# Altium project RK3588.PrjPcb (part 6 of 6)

## Sheet VSC_DP.SchDoc
size D; SheetNumber: 21; SheetTotal: 22
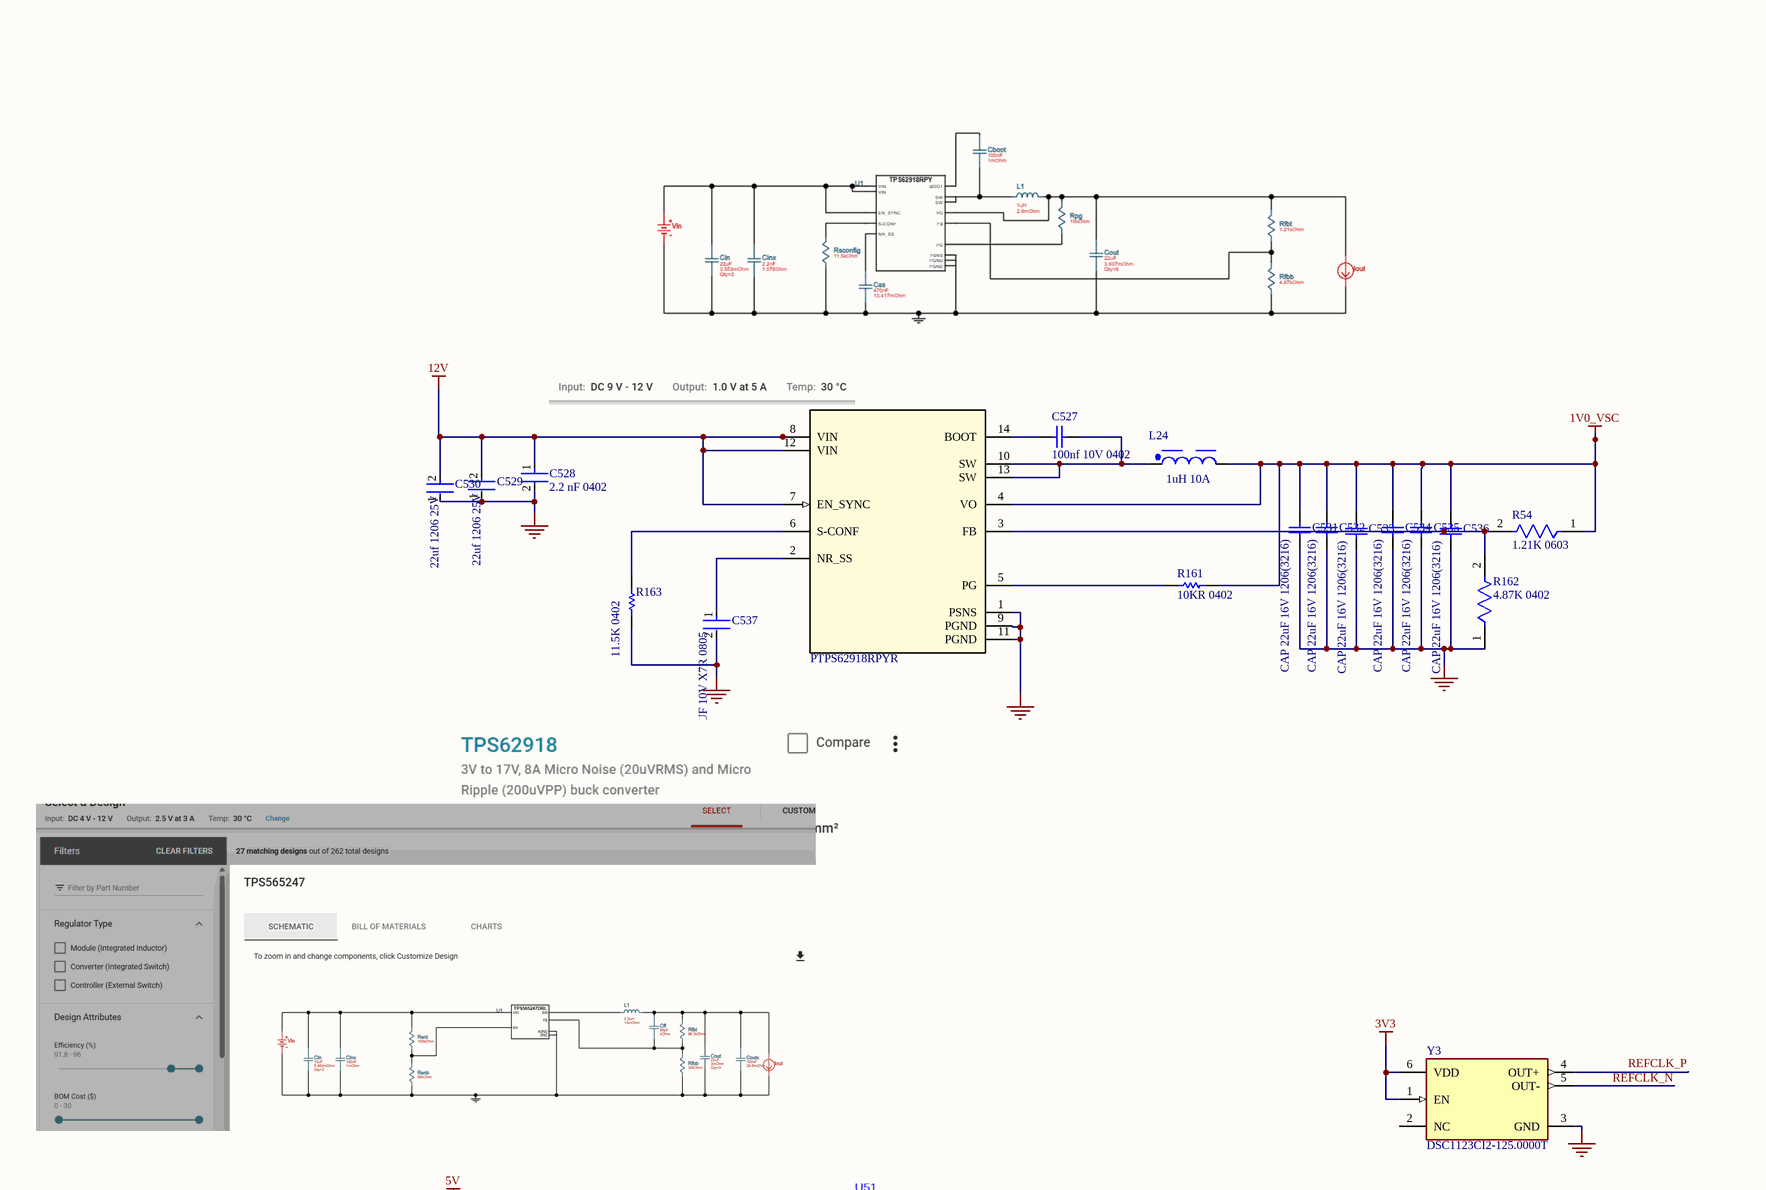
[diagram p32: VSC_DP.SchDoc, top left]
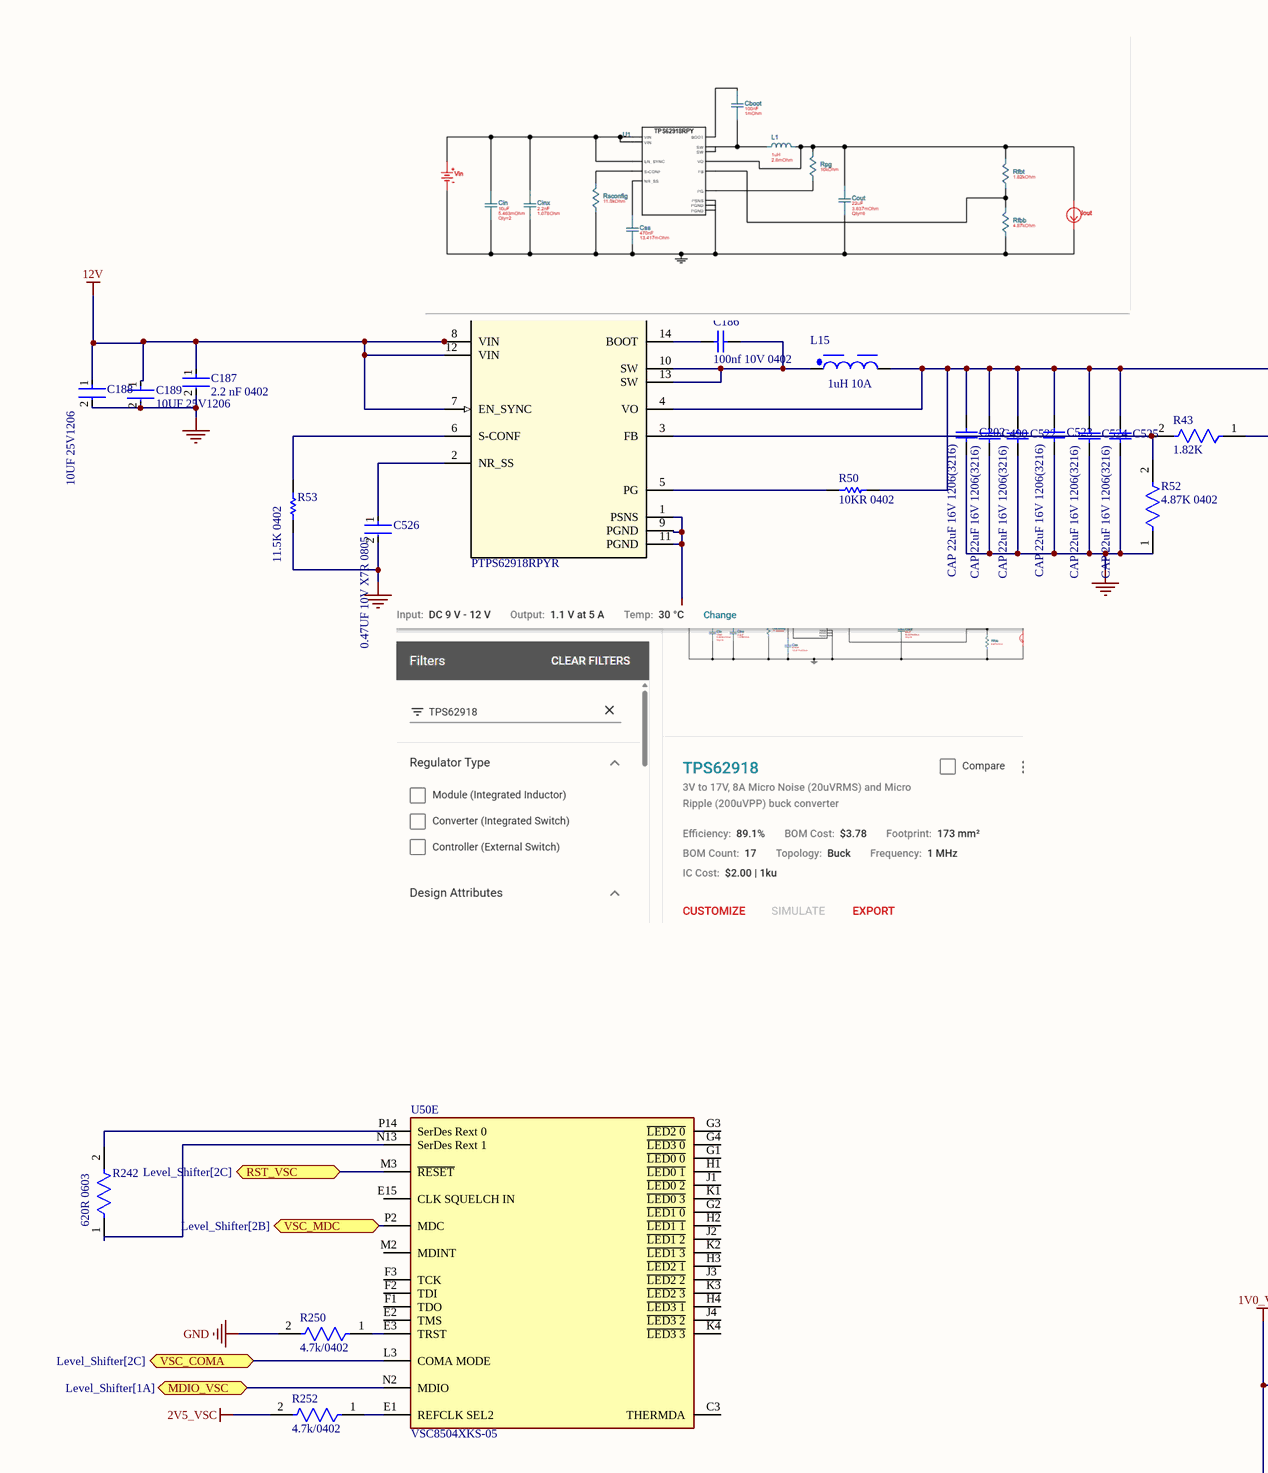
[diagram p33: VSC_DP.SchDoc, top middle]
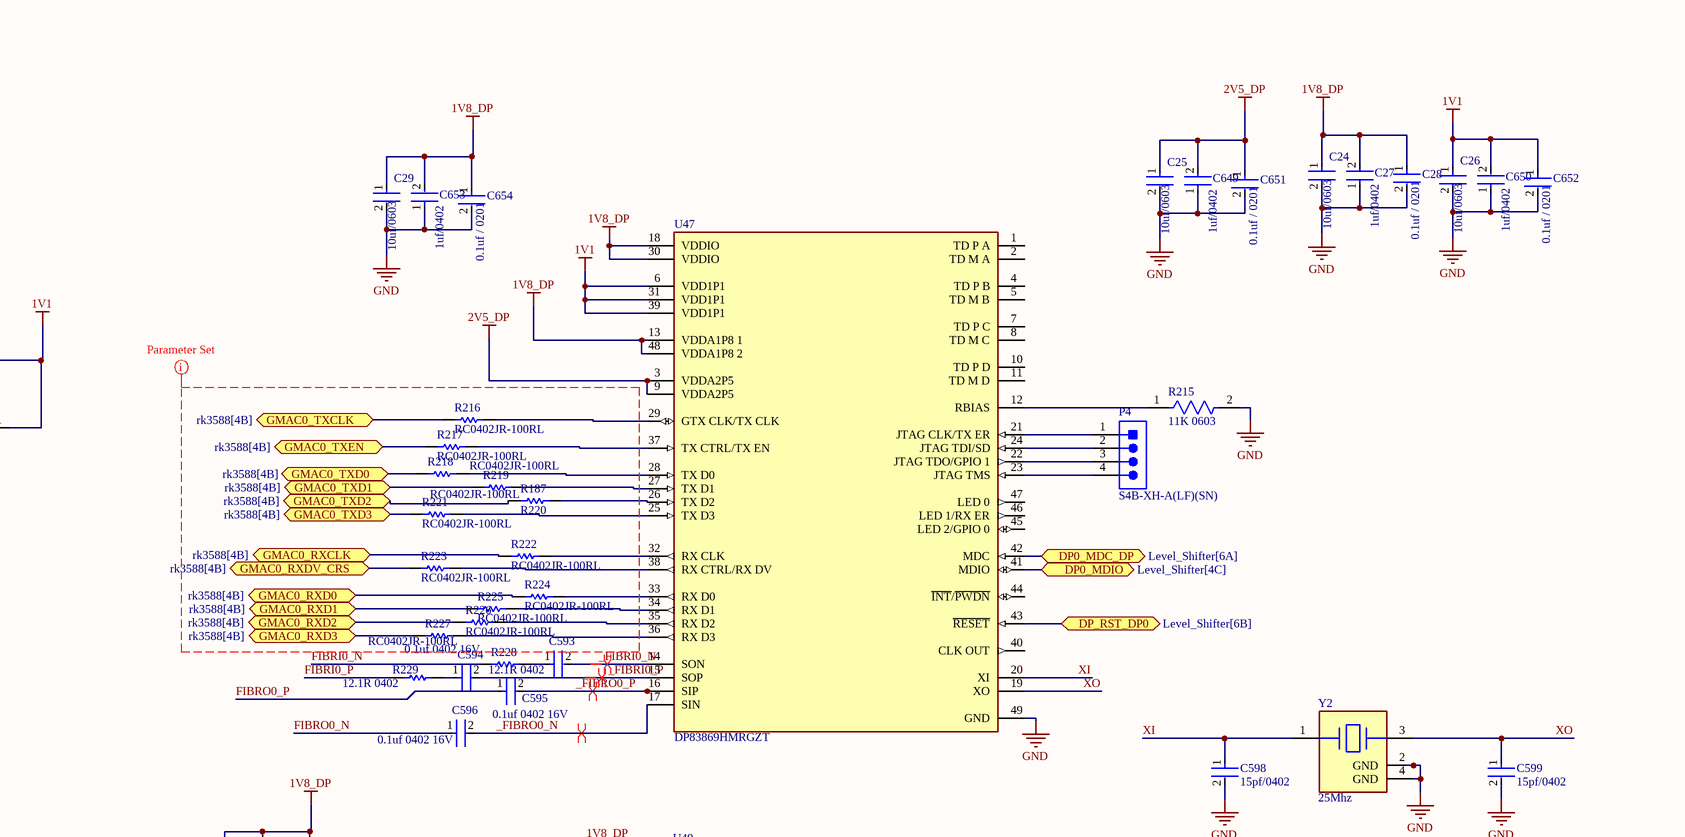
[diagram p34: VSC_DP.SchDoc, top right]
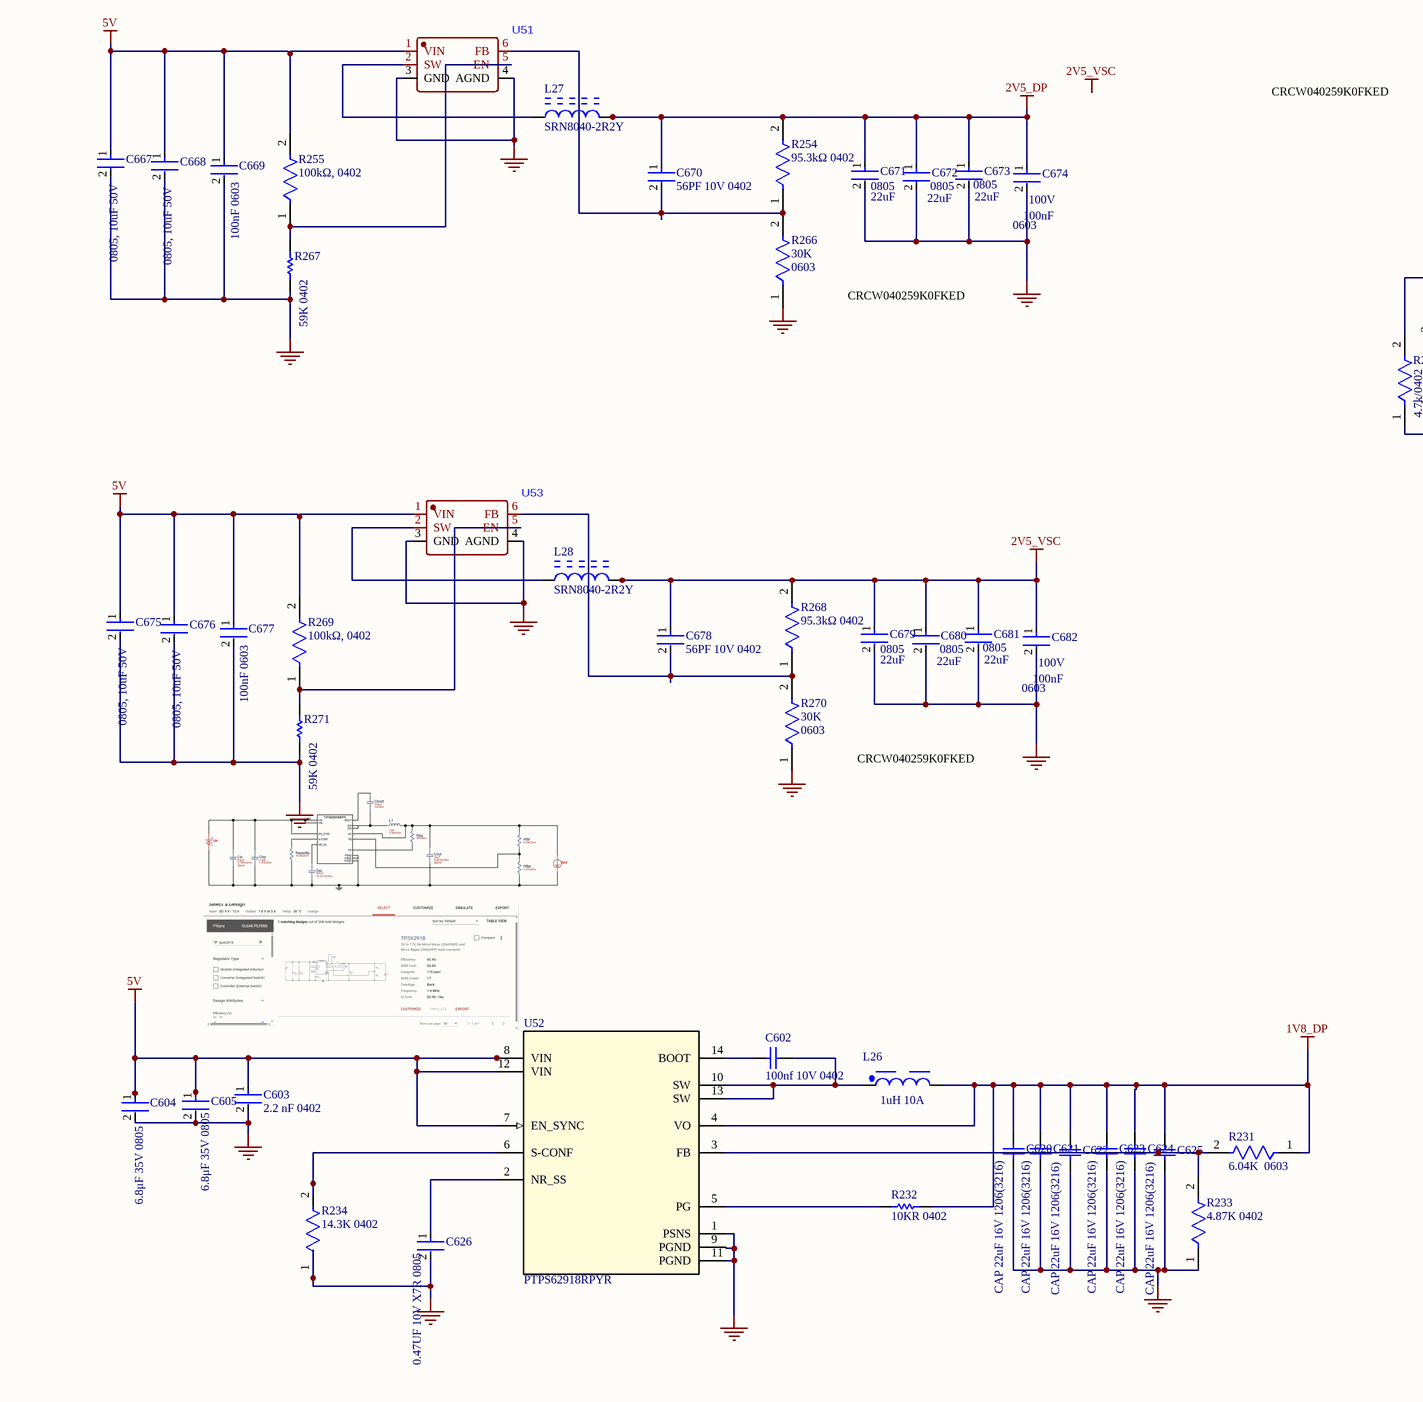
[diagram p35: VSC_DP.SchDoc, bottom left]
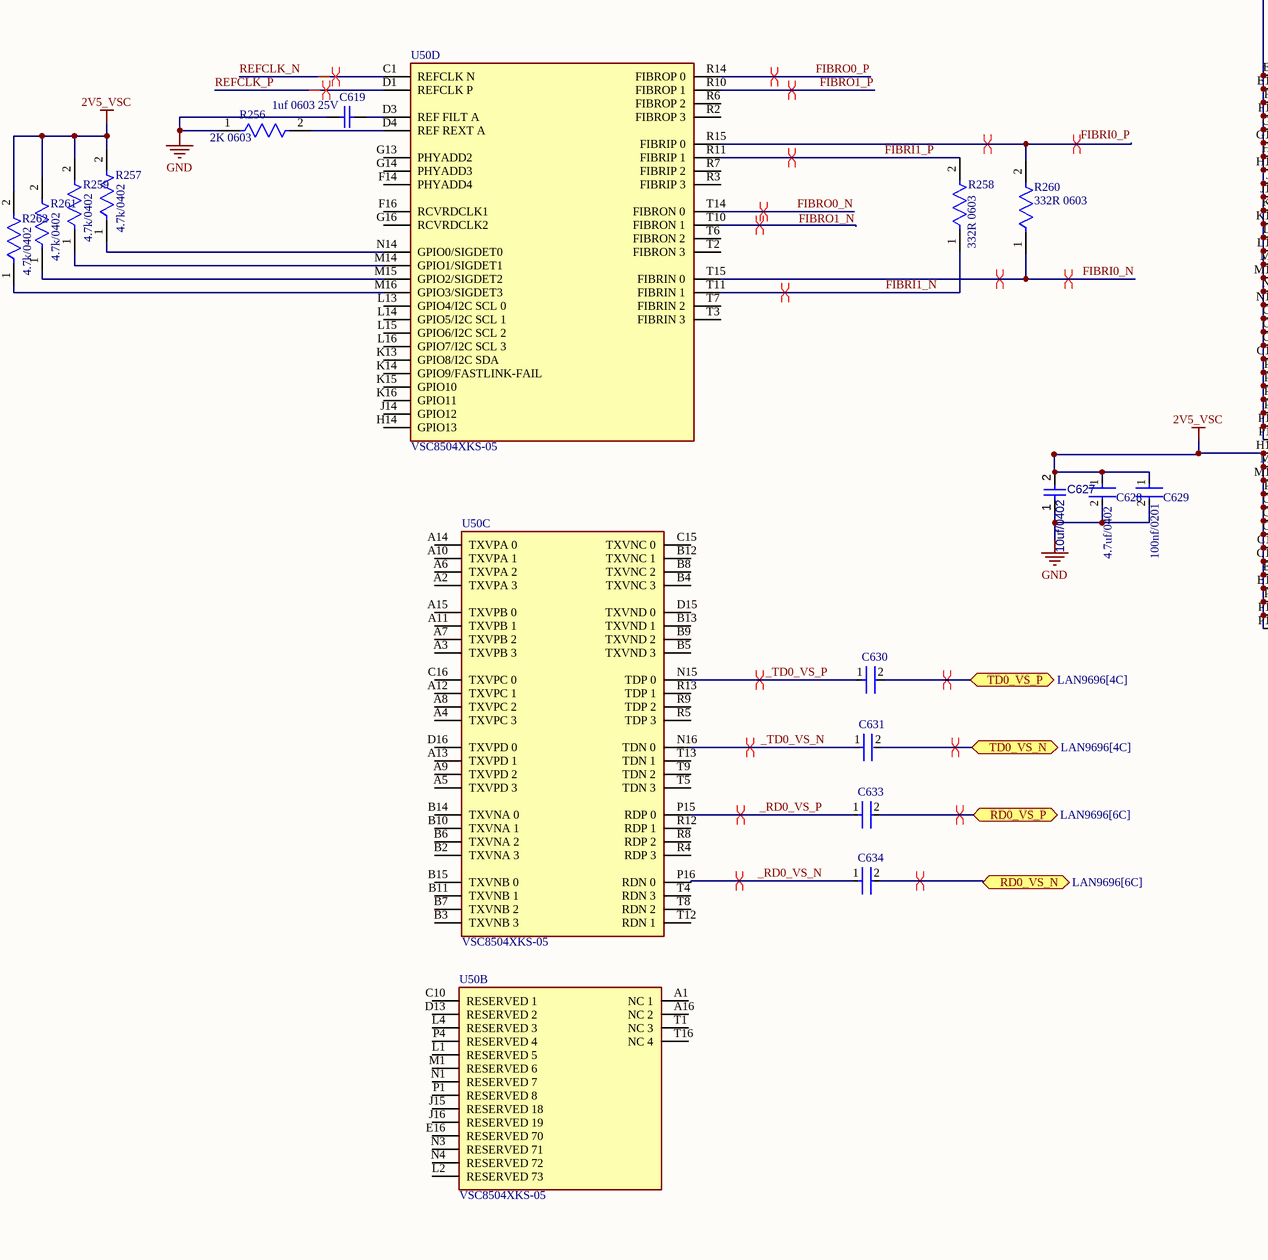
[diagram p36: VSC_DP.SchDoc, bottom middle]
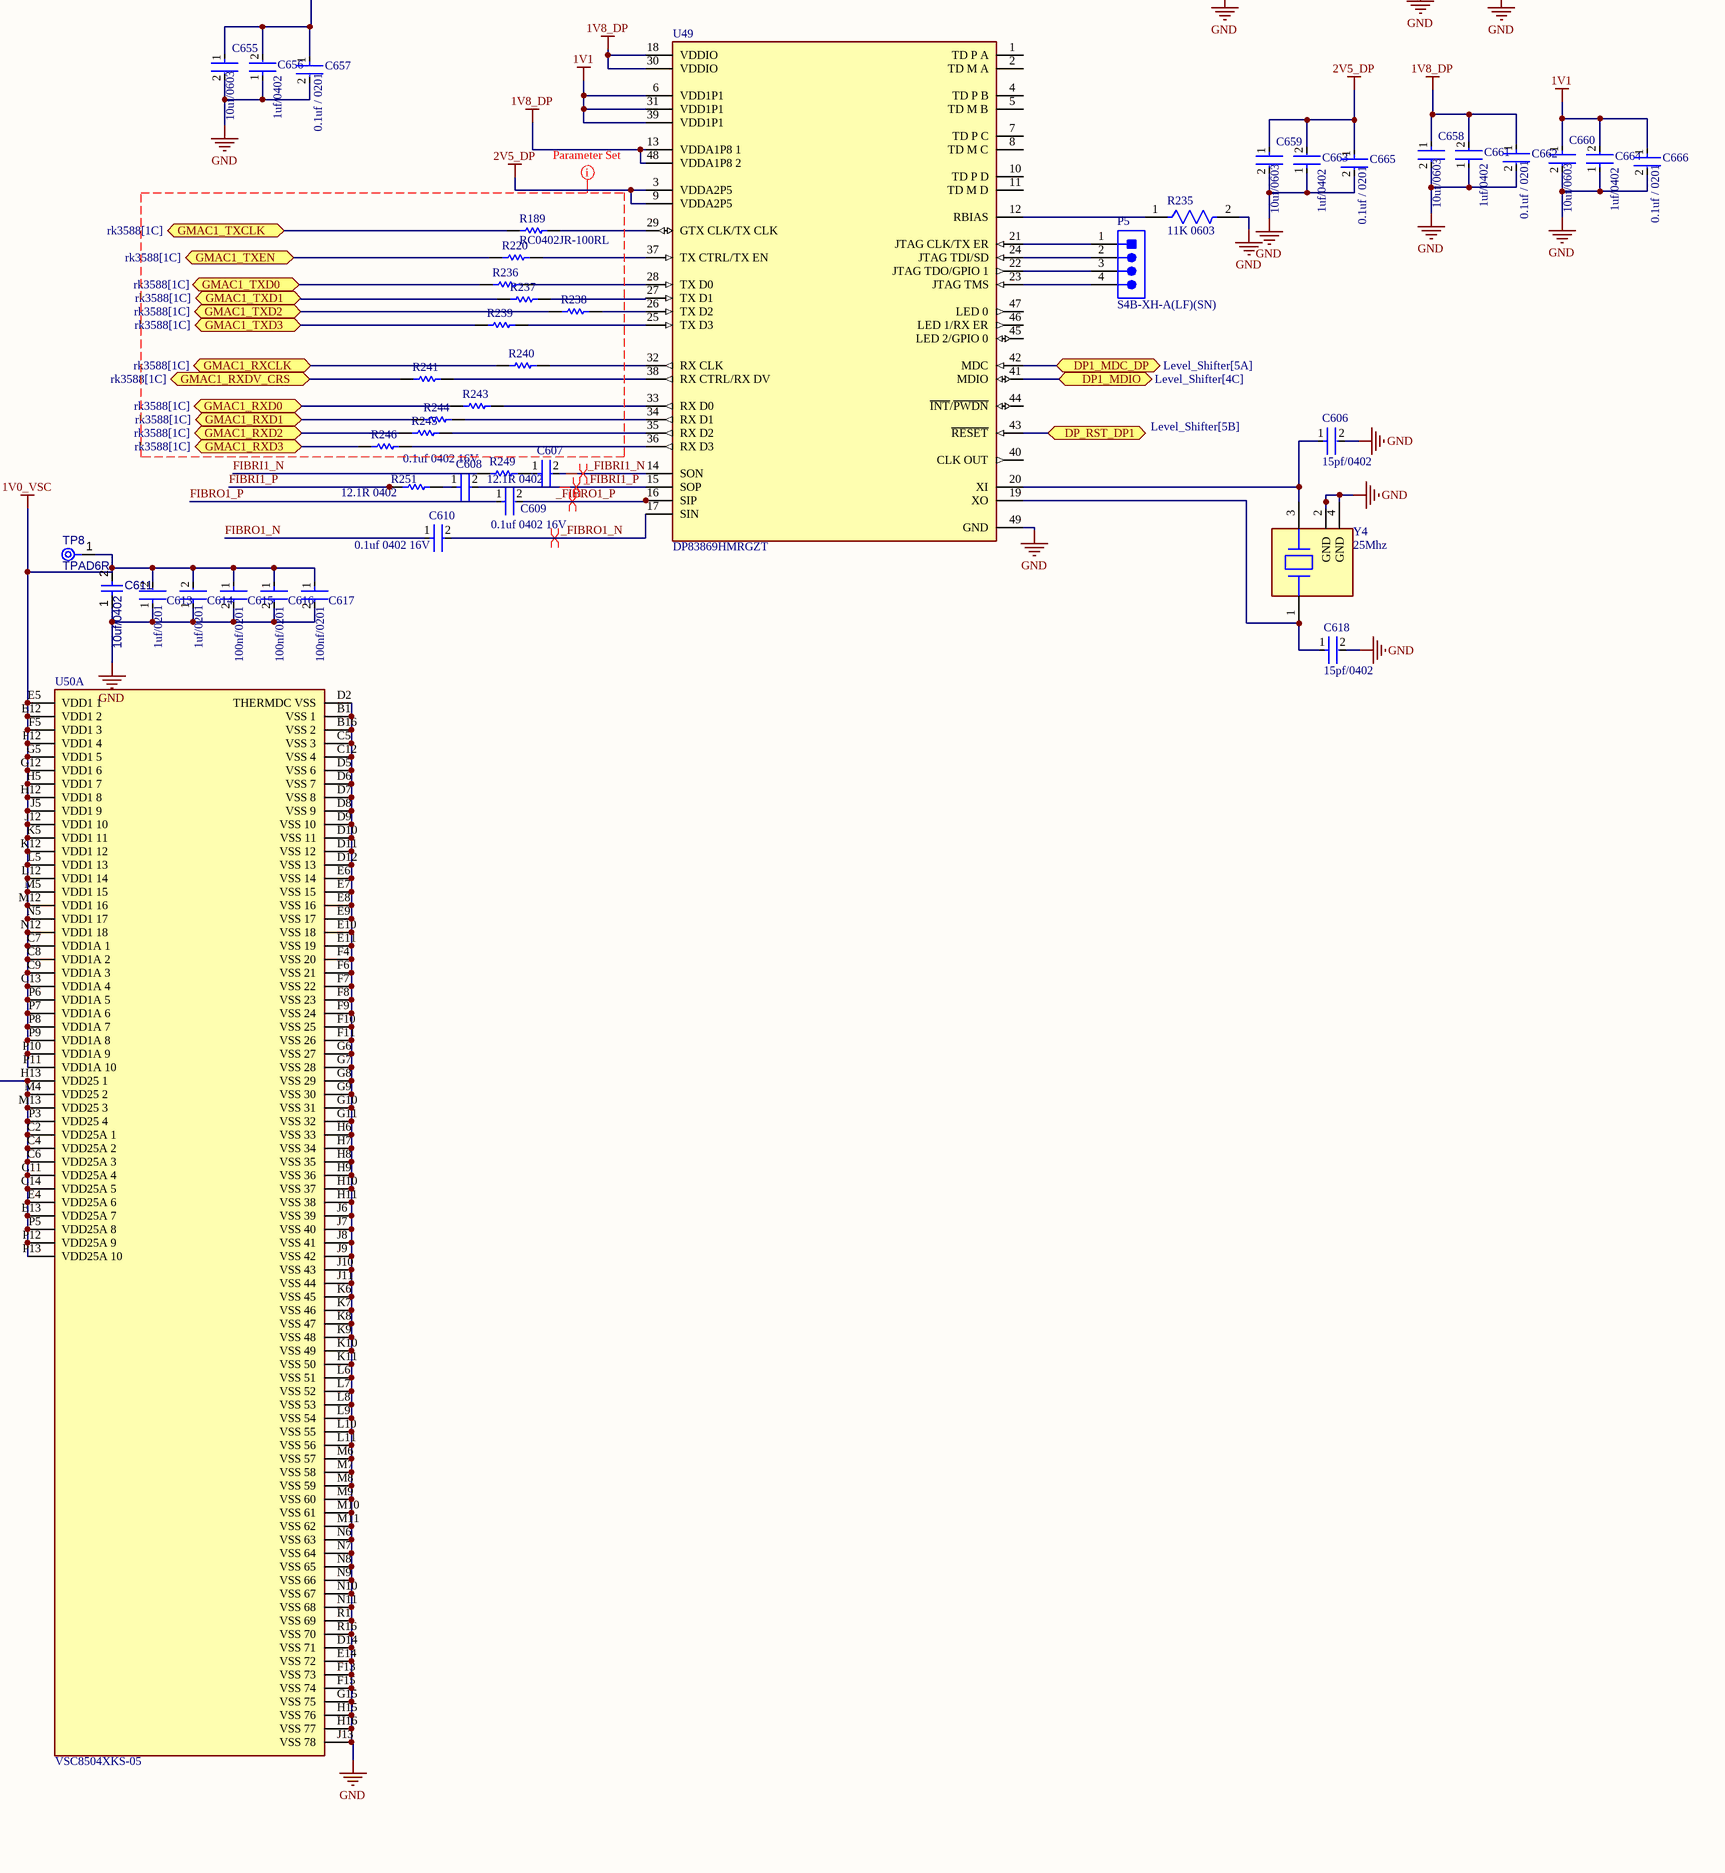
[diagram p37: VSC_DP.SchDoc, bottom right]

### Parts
C24  10uf/0603  [FP-CC0603-DC-MFG]
C25  10uf/0603  [FP-CC0603-DC-MFG]
C26  10uf/0603  [FP-CC0603-DC-MFG]
C27  1uf/0402  [FP-C0402C-BB-IPC_B]
C28  0.1uf / 0201  [FP-CC0201-BB-MFG]
C29  10uf/0603  [FP-CC0603-DC-MFG]
C186  100nf 10V 0402  [CAPC1005X55X25LL05T10]
C187  2.2 nF 0402  [FP-CGA2B-IPC_B]
C188  10UF 25V1206  [FP-C1206C-EH-MFG]
C189  10UF 25V1206  [FP-C1206C-EH-MFG]
C202  CAP 22uF 16V 1206(3216)  [CAPC1206(3216)190_L]
C490  CAP 22uF 16V 1206(3216)  [CAPC1206(3216)190_L]
C522  CAP 22uF 16V 1206(3216)  [CAPC1206(3216)190_L]
C523  CAP 22uF 16V 1206(3216)  [CAPC1206(3216)190_L]
C524  CAP 22uF 16V 1206(3216)  [CAPC1206(3216)190_L]
C525  CAP 22uF 16V 1206(3216)  [CAPC1206(3216)190_L]
C526  0.47UF 10V X7R 0805  [FP-C0805C-DN-MFG]
C527  100nf 10V 0402  [CAPC1005X55X25LL05T10]
C528  2.2 nF 0402  [FP-CGA2B-IPC_B]
C529  22uf 1206 25V  [FP-GRM31C-0_3-e0_3_0_8-IPC_A]
C530  22uf 1206 25V  [FP-GRM31C-0_3-e0_3_0_8-IPC_A]
C531  CAP 22uF 16V 1206(3216)  [CAPC1206(3216)190_L]
C532  CAP 22uF 16V 1206(3216)  [CAPC1206(3216)190_L]
C533  CAP 22uF 16V 1206(3216)  [CAPC1206(3216)190_L]
C534  CAP 22uF 16V 1206(3216)  [CAPC1206(3216)190_L]
C535  CAP 22uF 16V 1206(3216)  [CAPC1206(3216)190_L]
C536  CAP 22uF 16V 1206(3216)  [CAPC1206(3216)190_L]
C537  0.47UF 10V X7R 0805  [FP-C0805C-DN-MFG]
C593  0.1uf 0402 16V  [FP-C0402-BB-MFG]  (value not drawn)
C594  0.1uf 0402 16V  [FP-C0402-BB-MFG]
C595  0.1uf 0402 16V  [FP-C0402-BB-MFG]
C596  0.1uf 0402 16V  [FP-C0402-BB-MFG]
C598  15pf/0402  [FP-C0402-BB-MFG]
C599  15pf/0402  [FP-C0402-BB-MFG]
C602  100nf 10V 0402  [CAPC1005X55X25LL05T10]
C603  2.2 nF 0402  [FP-CGA2B-IPC_B]
C604  6.8μF 35V 0805  [FP-C2012-125-0_2-IPC_B]
C605  6.8μF 35V 0805  [FP-C2012-125-0_2-IPC_B]
C606  15pf/0402  [FP-C0402-BB-MFG]
C607  0.1uf 0402 16V  [FP-C0402-BB-MFG]  (value not drawn)
C608  0.1uf 0402 16V  [FP-C0402-BB-MFG]
C609  0.1uf 0402 16V  [FP-C0402-BB-MFG]
C610  0.1uf 0402 16V  [FP-C0402-BB-MFG]
C611  10uf/0402  [CAPC0402(1005)60_L]
C613  1uf/0201  [FP-CC0201-BA-MFG]
C614  1uf/0201  [FP-CC0201-BA-MFG]
C615  100nf/0201  [FP-CL03-IPC_C]
C616  100nf/0201  [FP-CL03-IPC_C]
C617  100nf/0201  [FP-CL03-IPC_C]
C618  15pf/0402  [FP-C0402-BB-MFG]
C619  1uf 0603 25V  [CAPC1608X95X35NL15T15]
C620  CAP 22uF 16V 1206(3216)  [CAPC1206(3216)190_L]
C621  CAP 22uF 16V 1206(3216)  [CAPC1206(3216)190_L]
C622  CAP 22uF 16V 1206(3216)  [CAPC1206(3216)190_L]
C623  CAP 22uF 16V 1206(3216)  [CAPC1206(3216)190_L]
C624  CAP 22uF 16V 1206(3216)  [CAPC1206(3216)190_L]
C625  CAP 22uF 16V 1206(3216)  [CAPC1206(3216)190_L]
C626  0.47UF 10V X7R 0805  [FP-C0805C-DN-MFG]
C627  10uf/0402  [CAPC0402(1005)60_L]
C628  4.7uf/0402  [FP-CC0402-MFG]
C629  100nf/0201  [FP-CL03-IPC_C]
C630  0.1uf 0402 16V  [FP-C0402-BB-MFG]  (value not drawn)
C631  0.1uf 0402 16V  [FP-C0402-BB-MFG]  (value not drawn)
C633  0.1uf 0402 16V  [FP-C0402-BB-MFG]  (value not drawn)
C634  0.1uf 0402 16V  [FP-C0402-BB-MFG]  (value not drawn)
C649  1uf/0402  [FP-C0402C-BB-IPC_B]
C650  1uf/0402  [FP-C0402C-BB-IPC_B]
C651  0.1uf / 0201  [FP-CC0201-BB-MFG]
C652  0.1uf / 0201  [FP-CC0201-BB-MFG]
C653  1uf/0402  [FP-C0402C-BB-IPC_B]
C654  0.1uf / 0201  [FP-CC0201-BB-MFG]
C655  10uf/0603  [FP-CC0603-DC-MFG]
C656  1uf/0402  [FP-C0402C-BB-IPC_B]
C657  0.1uf / 0201  [FP-CC0201-BB-MFG]
C658  10uf/0603  [FP-CC0603-DC-MFG]
C659  10uf/0603  [FP-CC0603-DC-MFG]
C660  10uf/0603  [FP-CC0603-DC-MFG]
C661  1uf/0402  [FP-C0402C-BB-IPC_B]
C662  0.1uf / 0201  [FP-CC0201-BB-MFG]
C663  1uf/0402  [FP-C0402C-BB-IPC_B]
C664  1uf/0402  [FP-C0402C-BB-IPC_B]
C665  0.1uf / 0201  [FP-CC0201-BB-MFG]
C666  0.1uf / 0201  [FP-CC0201-BB-MFG]
C667  0805, 10uF 50V  [FP-GRM21B-0_2-e0_2_0_7-IPC_C]
C668  0805, 10uF 50V  [FP-GRM21B-0_2-e0_2_0_7-IPC_C]
C669  100nF 0603  [FP-CGA3E-0_3-0_1-IPC_A]
C670  56PF 10V 0402  [FP-C0402-BB-MFG]
C671  Case/Package: 0805  Capacitance: 22uF  [FP-GRM21B-0_2-e0_2_0_7-IPC_C]  (hidden comment: GRM21BR61A226ME44L)
C672  Case/Package: 0805  Capacitance: 22uF  [FP-GRM21B-0_2-e0_2_0_7-IPC_C]  (hidden comment: GRM21BR61A226ME44L)
C673  Case/Package: 0805  Capacitance: 22uF  [FP-GRM21B-0_2-e0_2_0_7-IPC_C]  (hidden comment: GRM21BR61A226ME44L)
C674  Capacitance: 100nF  Case/Package: 0603  Voltage Rating: 100V  [FP-GRM188-0_1-e0_2_0_5-IPC_B]  (hidden comment: GRM188R72A104KA35D)
C675  0805, 10uF 50V  [FP-GRM21B-0_2-e0_2_0_7-IPC_C]
C676  0805, 10uF 50V  [FP-GRM21B-0_2-e0_2_0_7-IPC_C]
C677  100nF 0603  [FP-CGA3E-0_3-0_1-IPC_A]
C678  56PF 10V 0402  [FP-C0402-BB-MFG]
C679  Case/Package: 0805  Capacitance: 22uF  [FP-GRM21B-0_2-e0_2_0_7-IPC_C]  (hidden comment: GRM21BR61A226ME44L)
C680  Case/Package: 0805  Capacitance: 22uF  [FP-GRM21B-0_2-e0_2_0_7-IPC_C]  (hidden comment: GRM21BR61A226ME44L)
C681  Case/Package: 0805  Capacitance: 22uF  [FP-GRM21B-0_2-e0_2_0_7-IPC_C]  (hidden comment: GRM21BR61A226ME44L)
C682  Capacitance: 100nF  Case/Package: 0603  Voltage Rating: 100V  [FP-GRM188-0_1-e0_2_0_5-IPC_B]  (hidden comment: GRM188R72A104KA35D)
L15  1uH 10A  [WE-MAPI_4020]
L24  1uH 10A  [WE-MAPI_4020]
L26  1uH 10A  [WE-MAPI_4020]
L27  SRN8040-2R2Y  [BOUR-SRN8040_V]
L28  SRN8040-2R2Y  [BOUR-SRN8040_V]
P4  S4B-XH-A(LF)(SN)  [JST-S4B-XH-A(LF)(SN)_V]
P5  S4B-XH-A(LF)(SN)  [JST-S4B-XH-A(LF)(SN)_V]
R43  1.82K  [FP-CRCW0402-e3-IPC_A]
R50  10KR 0402  [RESC1005X40X25ML05T10]
R52  4.87K 0402  [FP-CRCW0402-e3-IPC_C]
R53  11.5K 0402  [RESC1005X40X25NL05T05]
R54  1.21K 0603  [FP-RMCF0603-IPC_B]
R161  10KR 0402  [RESC1005X40X25ML05T10]
R162  4.87K 0402  [FP-CRCW0402-e3-IPC_C]
R163  11.5K 0402  [RESC1005X40X25NL05T05]
R187  R220  [RESC1005X40X25NL05T10]
R189  RC0402JR-100RL  [RESC1005X40X25NL05T10]
R215  11K 0603  [FP-RT0603-MFG]
R216  RC0402JR-100RL  [RESC1005X40X25NL05T10]
R217  RC0402JR-100RL  [RESC1005X40X25NL05T10]
R218  RC0402JR-100RL  [RESC1005X40X25NL05T10]
R219  RC0402JR-100RL  [RESC1005X40X25NL05T10]
R220  RC0402JR-100RL  [RESC1005X40X25NL05T10]  (value not drawn)
R221  RC0402JR-100RL  [RESC1005X40X25NL05T10]
R222  RC0402JR-100RL  [RESC1005X40X25NL05T10]
R223  RC0402JR-100RL  [RESC1005X40X25NL05T10]
R224  RC0402JR-100RL  [RESC1005X40X25NL05T10]
R225  RC0402JR-100RL  [RESC1005X40X25NL05T10]
R226  RC0402JR-100RL  [RESC1005X40X25NL05T10]
R227  RC0402JR-100RL  [RESC1005X40X25NL05T10]
R228  12.1R 0402  [RESC1005X40X25LL05T10]
R229  12.1R 0402  [RESC1005X40X25LL05T10]
R231  6.04K  0603  [FP-RC0603-0_55-IPC_A]
R232  10KR 0402  [RESC1005X40X25ML05T10]
R233  4.87K 0402  [FP-CRCW0402-e3-IPC_C]
R234  14.3K 0402  [FP-CRCW0402-e3-MFG]
R235  11K 0603  [FP-RT0603-MFG]
R236  RC0402JR-100RL  [RESC1005X40X25NL05T10]  (value not drawn)
R237  RC0402JR-100RL  [RESC1005X40X25NL05T10]  (value not drawn)
R238  RC0402JR-100RL  [RESC1005X40X25NL05T10]  (value not drawn)
R239  RC0402JR-100RL  [RESC1005X40X25NL05T10]  (value not drawn)
R240  RC0402JR-100RL  [RESC1005X40X25NL05T10]  (value not drawn)
R241  RC0402JR-100RL  [RESC1005X40X25NL05T10]  (value not drawn)
R242  620R 0603  [FP-AC0603-IPC_C]
R243  RC0402JR-100RL  [RESC1005X40X25NL05T10]  (value not drawn)
R244  RC0402JR-100RL  [RESC1005X40X25NL05T10]  (value not drawn)
R245  RC0402JR-100RL  [RESC1005X40X25NL05T10]  (value not drawn)
R246  RC0402JR-100RL  [RESC1005X40X25NL05T10]  (value not drawn)
R249  12.1R 0402  [RESC1005X40X25LL05T10]
R250  4.7k/0402  [FP-MCS0402-IPC_A]
R251  12.1R 0402  [RESC1005X40X25LL05T10]
R252  4.7k/0402  [FP-MCS0402-IPC_A]
R254  95.3kΩ 0402  [FP-CRCW0402-e3-IPC_A]
R255  100kΩ, 0402  [FP-CRCW0402-e3-IPC_C]
R256  2K 0603  [FP-AC0603-IPC_B]
R257  4.7k/0402  [FP-MCS0402-IPC_A]
R258  332R 0603  [FP-RT0603-MFG]
R259  4.7k/0402  [FP-MCS0402-IPC_A]
R260  332R 0603  [FP-RT0603-MFG]
R261  4.7k/0402  [FP-MCS0402-IPC_A]
R262  4.7k/0402  [FP-MCS0402-IPC_A]
R266  value 30K  Case: 0603  [FP-MCT0603-MFG]
R267  59K 0402  [RESC1005X40X25LL05T05]
R268  95.3kΩ 0402  [FP-CRCW0402-e3-IPC_A]
R269  100kΩ, 0402  [FP-CRCW0402-e3-IPC_C]
R270  value 30K  Case: 0603  [FP-MCT0603-MFG]
R271  59K 0402  [RESC1005X40X25LL05T05]
TP8  TPAD6R  [TP06R]  (no BOM)
U9  PTPS62918RPYR  [RPY0014A-MFG]
U47  DP83869HMRGZT  [FP-RGZ0048B-IPC_A]
U48  PTPS62918RPYR  [RPY0014A-MFG]
U49  DP83869HMRGZT  [FP-RGZ0048B-IPC_A]
U50  VSC8504XKS-05  [FP-VSC8504XKS-05-IPC_C]  (parts A,B,C,D,E of 5)
U51  (no value)  [SOT-5X3-6_W1.6-L1.2-P0.50-LS1.6-BL]
U52  PTPS62918RPYR  [RPY0014A-MFG]
U53  (no value)  [SOT-5X3-6_W1.6-L1.2-P0.50-LS1.6-BL]
Y2  25Mhz  [FP-ABM8AIG-MFG]
Y3  DSC1123CI2-125.0000T  [FP-C04-1007-MFG]
Y4  25Mhz  [FP-ABM8AIG-MFG]

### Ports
DP0_MDC_DP (bidir, see Level_Shifter[6A]), DP0_MDIO (bidir, see Level_Shifter[4C]), DP1_MDC_DP (bidir, see Level_Shifter[5A]), DP1_MDIO (bidir, see Level_Shifter[4C]), DP_RST_DP0 (bidir, see Level_Shifter[6B]), DP_RST_DP1 (bidir, see Level_Shifter[5B]), GMAC0_RXCLK (bidir, see rk3588[4B]), GMAC0_RXD0 (bidir, see rk3588[4B]), GMAC0_RXD1 (bidir, see rk3588[4B]), GMAC0_RXD2 (bidir, see rk3588[4B]), GMAC0_RXD3 (bidir, see rk3588[4B]), GMAC0_RXDV_CRS (bidir, see rk3588[4B]), GMAC0_TXCLK (bidir, see rk3588[4B]), GMAC0_TXD0 (bidir, see rk3588[4B]), GMAC0_TXD1 (bidir, see rk3588[4B]), GMAC0_TXD2 (bidir, see rk3588[4B]), GMAC0_TXD3 (bidir, see rk3588[4B]), GMAC0_TXEN (bidir, see rk3588[4B]), GMAC1_RXCLK (bidir, see rk3588[1C]), GMAC1_RXD0 (bidir, see rk3588[1C]), GMAC1_RXD1 (bidir, see rk3588[1C]), GMAC1_RXD2 (bidir, see rk3588[1C]), GMAC1_RXD3 (bidir, see rk3588[1C]), GMAC1_RXDV_CRS (bidir, see rk3588[1C]), GMAC1_TXCLK (bidir, see rk3588[1C]), GMAC1_TXD0 (bidir, see rk3588[1C]), GMAC1_TXD1 (bidir, see rk3588[1C]), GMAC1_TXD2 (bidir, see rk3588[1C]), GMAC1_TXD3 (bidir, see rk3588[1C]), GMAC1_TXEN (bidir, see rk3588[1C]), MDIO_VSC (bidir, see Level_Shifter[1A]), RD0_VS_N (bidir, see LAN9696[6C]), RD0_VS_P (bidir, see LAN9696[6C]), RST_VSC (bidir, see Level_Shifter[2C]), TD0_VS_N (bidir, see LAN9696[4C]), TD0_VS_P (bidir, see LAN9696[4C]), VSC_COMA (bidir, see Level_Shifter[2C]), VSC_MDC (bidir, see Level_Shifter[2B])

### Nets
1V0_VSC: C531.2 C532.2 C533.2 C534.2 C535.2 C536.2 C611.2 C613.2 C614.2 C615.1 C616.1 C617.1 L24.2 R54.1 R161.1 TP8.1(TP) U48.4(VO) U50.C7(VDD1A_1) U50.C8(VDD1A_2) U50.C9(VDD1A_3) U50.C13(VDD1A_4) U50.E5(VDD1_1) U50.E12(VDD1_2) U50.F5(VDD1_3) U50.F12(VDD1_4) U50.G5(VDD1_5) U50.G12(VDD1_6) U50.H5(VDD1_7) U50.H12(VDD1_8) U50.J5(VDD1_9) U50.J12(VDD1_10) U50.K5(VDD1_11) U50.K12(VDD1_12) U50.L5(VDD1_13) U50.L12(VDD1_14) U50.M5(VDD1_15) U50.M12(VDD1_16) U50.N5(VDD1_17) U50.N12(VDD1_18) U50.P6(VDD1A_5) U50.P7(VDD1A_6) U50.P8(VDD1A_7) U50.P9(VDD1A_8) U50.P10(VDD1A_9) U50.P11(VDD1A_10)
1V1: C26.1 C202.2 C490.2 C522.2 C523.2 C524.2 C525.2 C650.2 C652.1 C660.1 C664.2 C666.1 L15.2 R43.1 R50.1 U9.4(VO) U47.6(VDD1P1) U47.31(VDD1P1) U47.39(VDD1P1) U49.6(VDD1P1) U49.31(VDD1P1) U49.39(VDD1P1)
1V8_DP: C24.1 C27.2 C28.1 C29.1 C620.2 C621.2 C622.2 C623.2 C624.2 C625.2 C653.2 C654.1 C655.1 C656.2 C657.1 C658.1 C661.2 C662.1 L26.2 R231.1 R232.1 U47.13(VDDA1P8_1) U47.18(VDDIO) U47.30(VDDIO) U47.48(VDDA1P8_2) U49.13(VDDA1P8_1) U49.18(VDDIO) U49.30(VDDIO) U49.48(VDDA1P8_2) U52.4(VO)
2V5_DP: C25.1 C649.2 C651.1 C659.1 C663.2 C665.1 C670.1 C671.1 C672.1 C673.1 C674.1 L27.2 R254.2 U47.3(VDDA2P5) U47.9(VDDA2P5) U49.3(VDDA2P5) U49.9(VDDA2P5)
2V5_VSC: C627.2 C628.1 C629.1 C678.1 C679.1 C680.1 C681.1 C682.1 L28.2 R252.2 R257.2 R259.2 R261.2 R262.2 R268.2 U50.C2(VDD25A_1) U50.C4(VDD25A_2) U50.C6(VDD25A_3) U50.C11(VDD25A_4) U50.C14(VDD25A_5) U50.E4(VDD25A_6) U50.E13(VDD25A_7) U50.H13(VDD25_1) U50.M4(VDD25_2) U50.M13(VDD25_3) U50.P3(VDD25_4) U50.P5(VDD25A_8) U50.P12(VDD25A_9) U50.P13(VDD25A_10)
3V3: Y3.1(EN) Y3.6(VDD)
5V: C603.1 C604.1 C605.1 C667.1 C668.1 C669.1 C675.1 C676.1 C677.1 R255.2 R269.2 U51.1(VIN) U52.7(EN_SYNC) U52.8(VIN) U52.12(VIN) U53.1(VIN)
12V: C187.1 C188.1 C189.1 C528.1 C529.2 C530.2 U9.7(EN_SYNC) U9.8(VIN) U9.12(VIN) U48.7(EN_SYNC) U48.8(VIN) U48.12(VIN)
GND: C24.2 C25.2 C26.2 C27.1 C28.2 C29.2 C187.2 C188.2 C189.2 C202.1 C490.1 C522.1 C523.1 C524.1 C525.1 C526.2 C528.2 C529.1 C530.1 C531.1 C532.1 C533.1 C534.1 C535.1 C536.1 C537.2 C598.2 C599.2 C603.2 C604.2 C605.2 C606.2 C611.1 C613.1 C614.1 C615.2 C616.2 C617.2 C618.2 C619.1 C620.1 C621.1 C622.1 C623.1 C624.1 C625.1 C626.2 C627.1 C628.2 C629.2 C649.1 C650.1 C651.2 C652.2 C653.1 C654.2 C655.2 C656.1 C657.2 C658.2 C659.2 C660.2 C661.1 C662.2 C663.1 C664.1 C665.2 C666.2 C667.2 C668.2 C669.2 C671.2 C672.2 C673.2 C674.2 C675.2 C676.2 C677.2 C679.2 C680.2 C681.2 C682.2 R52.1 R53.1 R162.1 R163.1 R215.2 R233.1 R234.1 R235.2 R250.2 R256.1 R266.1 R267.1 R270.1 R271.1 U9.1(PSNS) U9.9(PGND) U9.11(PGND) U47.49(GND) U48.1(PSNS) U48.9(PGND) U48.11(PGND) U49.49(GND) U50.B1(VSS_1) U50.B16(VSS_2) U50.C5(VSS_3) U50.C12(VSS_4) U50.D2(THERMDC_VSS) U50.D5(VSS_6) U50.D6(VSS_7) U50.D7(VSS_8) U50.D8(VSS_9) U50.D9(VSS_10) U50.D10(VSS_11) U50.D11(VSS_12) U50.D12(VSS_13) U50.D14(VSS_71) U50.E6(VSS_14) U50.E7(VSS_15) U50.E8(VSS_16) U50.E9(VSS_17) U50.E10(VSS_18) U50.E11(VSS_19) U50.E14(VSS_72) U50.F4(VSS_20) U50.F6(VSS_21) U50.F7(VSS_22) U50.F8(VSS_23) U50.F9(VSS_24) U50.F10(VSS_25) U50.F11(VSS_26) U50.F13(VSS_73) U50.F15(VSS_74) U50.G6(VSS_27) U50.G7(VSS_28) U50.G8(VSS_29) U50.G9(VSS_30) U50.G10(VSS_31) U50.G11(VSS_32) U50.G15(VSS_75) U50.H6(VSS_33) U50.H7(VSS_34) U50.H8(VSS_35) U50.H9(VSS_36) U50.H10(VSS_37) U50.H11(VSS_38) U50.H15(VSS_76) U50.H16(VSS_77) U50.J6(VSS_39) U50.J7(VSS_40) U50.J8(VSS_41) U50.J9(VSS_42) U50.J10(VSS_43) U50.J11(VSS_44) U50.J13(VSS_78) U50.K6(VSS_45) U50.K7(VSS_46) U50.K8(VSS_47) U50.K9(VSS_48) U50.K10(VSS_49) U50.K11(VSS_50) U50.L6(VSS_51) U50.L7(VSS_52) U50.L8(VSS_53) U50.L9(VSS_54) U50.L10(VSS_55) U50.L11(VSS_56) U50.M6(VSS_57) U50.M7(VSS_58) U50.M8(VSS_59) U50.M9(VSS_60) U50.M10(VSS_61) U50.M11(VSS_62) U50.N6(VSS_63) U50.N7(VSS_64) U50.N8(VSS_65) U50.N9(VSS_66) U50.N10(VSS_67) U50.N11(VSS_68) U50.R1(VSS_69) U50.R16(VSS_70) U51.3(GND) U51.4(AGND) U52.1(PSNS) U52.9(PGND) U52.11(PGND) U53.3(GND) U53.4(AGND) Y2.2(GND) Y2.4(GND) Y3.3(GND) Y4.2(GND) Y4.4(GND)
_FIBRI0_N: C593.2 U47.14(SON)
_FIBRI0_P: C594.2 U47.15(SOP)
_FIBRI1_N: C607.2 U49.14(SON)
_FIBRI1_P: C608.2 U49.15(SOP)
_FIBRO0_N: C596.2 U47.17(SIN)
_FIBRO0_P: C595.2 U47.16(SIP)
_FIBRO1_N: C610.2 U49.17(SIN)
_FIBRO1_P: C609.2 U49.16(SIP)
_RD0_VS_N: C634.1 U50.P16(RDN_0)
_RD0_VS_P: C633.1 U50.P15(RDP_0)
_TD0_VS_N: C631.1 U50.N16(TDN_0)
_TD0_VS_P: C630.1 U50.N15(TDP_0)
DP0_MDC_DP: U47.42(MDC) ; port DP0_MDC_DP
DP0_MDIO: U47.41(MDIO) ; port DP0_MDIO
DP1_MDC_DP: U49.42(MDC) ; port DP1_MDC_DP
DP1_MDIO: U49.41(MDIO) ; port DP1_MDIO
DP_RST_DP0: U47.43(~{RESET}) ; port DP_RST_DP0
DP_RST_DP1: U49.43(~{RESET}) ; port DP_RST_DP1
FIBRI0_N: R228.1 R260.1 U50.T15(FIBRIN_0)
FIBRI0_P: R229.1 R260.2 U50.R15(FIBRIP_0)
FIBRI1_N: R249.1 R258.1 U50.T11(FIBRIN_1)
FIBRI1_P: R251.1 R258.2 U50.R11(FIBRIP_1)
FIBRO0_N: C596.1 U50.T14(FIBRON_0)
FIBRO0_P: C595.1 U50.R14(FIBROP_0)
FIBRO1_N: C610.1 U50.T10(FIBRON_1)
FIBRO1_P: C609.1 U50.R10(FIBROP_1)
GMAC0_RXCLK: R222.1 ; port GMAC0_RXCLK
GMAC0_RXD0: R224.1 ; port GMAC0_RXD0
GMAC0_RXD1: R225.1 ; port GMAC0_RXD1
GMAC0_RXD2: R226.1 ; port GMAC0_RXD2
GMAC0_RXD3: R227.1 ; port GMAC0_RXD3
GMAC0_RXDV_CRS: R223.1 ; port GMAC0_RXDV_CRS
GMAC0_TXCLK: R216.1 ; port GMAC0_TXCLK
GMAC0_TXD0: R218.1 ; port GMAC0_TXD0
GMAC0_TXD1: R219.1 ; port GMAC0_TXD1
GMAC0_TXD2: R187.1 ; port GMAC0_TXD2
GMAC0_TXD3: R221.1 ; port GMAC0_TXD3
GMAC0_TXEN: R217.1 ; port GMAC0_TXEN
GMAC1_RXCLK: R240.1 ; port GMAC1_RXCLK
GMAC1_RXD0: R243.1 ; port GMAC1_RXD0
GMAC1_RXD1: R244.1 ; port GMAC1_RXD1
GMAC1_RXD2: R245.1 ; port GMAC1_RXD2
GMAC1_RXD3: R246.1 ; port GMAC1_RXD3
GMAC1_RXDV_CRS: R241.1 ; port GMAC1_RXDV_CRS
GMAC1_TXCLK: R189.1 ; port GMAC1_TXCLK
GMAC1_TXD0: R236.1 ; port GMAC1_TXD0
GMAC1_TXD1: R237.1 ; port GMAC1_TXD1
GMAC1_TXD2: R238.1 ; port GMAC1_TXD2
GMAC1_TXD3: R239.1 ; port GMAC1_TXD3
GMAC1_TXEN: R220.1 ; port GMAC1_TXEN
MDIO_VSC: U50.N2(MDIO) ; port MDIO_VSC
RD0_VS_N: C634.2 ; port RD0_VS_N
RD0_VS_P: C633.2 ; port RD0_VS_P
REFCLK_N: U50.C1(REFCLK_N) Y3.5(OUT-)
REFCLK_P: U50.D1(REFCLK_P) Y3.4(OUT+)
RST_VSC: U50.M3(~{RESET}) ; port RST_VSC
TD0_VS_N: C631.2 ; port TD0_VS_N
TD0_VS_P: C630.2 ; port TD0_VS_P
VSC_COMA: U50.L3(COMA_MODE) ; port VSC_COMA
VSC_MDC: U50.P2(MDC) ; port VSC_MDC
XI: C598.1 U47.20(XI) Y2.1
XO: C599.1 U47.19(XO) Y2.3
NetC186_1: C186.1 U9.14(BOOT)
NetC186_2: C186.2 L15.1 U9.10(SW) U9.13(SW)
NetC526_1: C526.1 U9.2(NR_SS)
NetC527_1: C527.1 U48.14(BOOT)
NetC527_2: C527.2 L24.1 U48.10(SW) U48.13(SW)
NetC537_1: C537.1 U48.2(NR_SS)
NetC593_1: C593.1 R228.2
NetC594_1: C594.1 R229.2
NetC602_1: C602.1 U52.14(BOOT)
NetC602_2: C602.2 L26.1 U52.10(SW) U52.13(SW)
NetC606_1: C606.1 U49.20(XI) Y4.3
NetC607_1: C607.1 R249.2
NetC608_1: C608.1 R251.2
NetC618_1: C618.1 U49.19(XO) Y4.1
NetC619_2: C619.2 U50.D3(REF_FILT_A)
NetC626_1: C626.1 U52.2(NR_SS)
NetC670_2: C670.2 R254.1 R266.2 U51.6(FB)
NetC678_2: C678.2 R268.1 R270.2 U53.6(FB)
NetL27_1: L27.1 U51.2(SW)
NetL28_1: L28.1 U53.2(SW)
NetP4_1: P4.1 U47.21(JTAG_CLK/TX_ER)
NetP4_2: P4.2 U47.24(JTAG_TDI/SD)
NetP4_3: P4.3 U47.22(JTAG_TDO/GPIO_1)
NetP4_4: P4.4 U47.23(JTAG_TMS)
NetP5_1: P5.1 U49.21(JTAG_CLK/TX_ER)
NetP5_2: P5.2 U49.24(JTAG_TDI/SD)
NetP5_3: P5.3 U49.22(JTAG_TDO/GPIO_1)
NetP5_4: P5.4 U49.23(JTAG_TMS)
NetR43_2: R43.2 R52.2 U9.3(FB)
NetR50_2: R50.2 U9.5(PG)
NetR53_2: R53.2 U9.6(S-CONF)
NetR54_2: R54.2 R162.2 U48.3(FB)
NetR161_2: R161.2 U48.5(PG)
NetR163_2: R163.2 U48.6(S-CONF)
NetR187_2: R187.2 U47.26(TX_D2)
NetR189_2: R189.2 U49.29(GTX_CLK/TX_CLK)
NetR215_1: R215.1 U47.12(RBIAS)
NetR216_2: R216.2 U47.29(GTX_CLK/TX_CLK)
NetR217_2: R217.2 U47.37(TX_CTRL/TX_EN)
NetR218_2: R218.2 U47.28(TX_D0)
NetR219_2: R219.2 U47.27(TX_D1)
NetR220_2: R220.2 U49.37(TX_CTRL/TX_EN)
NetR221_2: R221.2 U47.25(TX_D3)
NetR222_2: R222.2 U47.32(RX_CLK)
NetR223_2: R223.2 U47.38(RX_CTRL/RX_DV)
NetR224_2: R224.2 U47.33(RX_D0)
NetR225_2: R225.2 U47.34(RX_D1)
NetR226_2: R226.2 U47.35(RX_D2)
NetR227_2: R227.2 U47.36(RX_D3)
NetR231_2: R231.2 R233.2 U52.3(FB)
NetR232_2: R232.2 U52.5(PG)
NetR234_2: R234.2 U52.6(S-CONF)
NetR235_1: R235.1 U49.12(RBIAS)
NetR236_2: R236.2 U49.28(TX_D0)
NetR237_2: R237.2 U49.27(TX_D1)
NetR238_2: R238.2 U49.26(TX_D2)
NetR239_2: R239.2 U49.25(TX_D3)
NetR240_2: R240.2 U49.32(RX_CLK)
NetR241_2: R241.2 U49.38(RX_CTRL/RX_DV)
NetR242_1: R242.1 U50.N13(SerDes_Rext_1)
NetR242_2: R242.2 U50.P14(SerDes_Rext_0)
NetR243_2: R243.2 U49.33(RX_D0)
NetR244_2: R244.2 U49.34(RX_D1)
NetR245_2: R245.2 U49.35(RX_D2)
NetR246_2: R246.2 U49.36(RX_D3)
NetR250_1: R250.1 U50.E3(TRST)
NetR252_1: R252.1 U50.E1(REFCLK_SEL2)
NetR255_1: R255.1 R267.2 U51.5(EN)
NetR256_2: R256.2 U50.D4(REF_REXT_A)
NetR257_1: R257.1 U50.N14(GPIO0/SIGDET0)
NetR259_1: R259.1 U50.M14(GPIO1/SIGDET1)
NetR261_1: R261.1 U50.M15(GPIO2/SIGDET2)
NetR262_1: R262.1 U50.M16(GPIO3/SIGDET3)
NetR269_1: R269.1 R271.2 U53.5(EN)

Not connected (* = marked no-connect by the designer): U47 1(TD_P_A) 2(TD_M_A) 4(TD_P_B) 5(TD_M_B) 7(TD_P_C) 8(TD_M_C) 10(TD_P_D) 11(TD_M_D) 40(CLK_OUT) 44(~{INT}/~{PWDN}) 45(LED_2/GPIO_0) 46(LED_1/RX_ER) 47(LED_0); U49 1(TD_P_A) 2(TD_M_A) 4(TD_P_B) 5(TD_M_B) 7(TD_P_C) 8(TD_M_C) 10(TD_P_D) 11(TD_M_D) 40(CLK_OUT) 44(~{INT}/~{PWDN}) 45(LED_2/GPIO_0) 46(LED_1/RX_ER) 47(LED_0); U50 A1(NC_1) A2(TXVPA_3) A3(TXVPB_3) A4(TXVPC_3) A5(TXVPD_3) A6(TXVPA_2) A7(TXVPB_2) A8(TXVPC_2) A9(TXVPD_2) A10(TXVPA_1) A11(TXVPB_1) A12(TXVPC_1) A13(TXVPD_1) A14(TXVPA_0) A15(TXVPB_0) A16(NC_2) B2(TXVNA_3) B3(TXVNB_3) B4(TXVNC_3) B5(TXVND_3) B6(TXVNA_2) B7(TXVNB_2) B8(TXVNC_2) B9(TXVND_2) B10(TXVNA_1) B11(TXVNB_1) B12(TXVNC_1) B13(TXVND_1) B14(TXVNA_0) B15(TXVNB_0) C3(THERMDA) C10(RESERVED_1) C15(TXVNC_0) C16(TXVPC_0) D13(RESERVED_2) D15(TXVND_0) D16(TXVPD_0) E2(TMS) E15(CLK_SQUELCH_IN) E16(RESERVED_70) F1(TDO) F2(TDI) F3(TCK) F14(PHYADD4) F16(RCVRDCLK1) G1(~{LED0_0}) G2(~{LED1_0}) G3(~{LED2_0}) G4(~{LED3_0}) G13(PHYADD2) G14(PHYADD3) G16(RCVRDCLK2) H1(~{LED0_1}) H2(~{LED1_1}) H3(~{LED2_1}) H4(~{LED3_1}) H14(GPIO13) J1(~{LED0_2}) J2(~{LED1_2}) J3(~{LED2_2}) J4(~{LED3_2}) J14(GPIO12) J15(RESERVED_18) J16(RESERVED_19) K1(~{LED0_3}) K2(~{LED1_3}) K3(~{LED2_3}) K4(~{LED3_3}) K13(GPIO8/I2C_SDA) K14(GPIO9/FASTLINK-FAIL) K15(GPIO10) K16(GPIO11) L1(RESERVED_5) L2(RESERVED_73) L4(RESERVED_3) L13(GPIO4/I2C_SCL_0) L14(GPIO5/I2C_SCL_1) L15(GPIO6/I2C_SCL_2) L16(GPIO7/I2C_SCL_3) M1(RESERVED_6) M2(MDINT) N1(RESERVED_7) N3(RESERVED_71) N4(RESERVED_72) P1(RESERVED_8) P4(RESERVED_4) R2(FIBROP_3) R3(FIBRIP_3) R4(RDP_3) R5(TDP_3) R6(FIBROP_2) R7(FIBRIP_2) R8(RDP_2) R9(TDP_2) R12(RDP_1) R13(TDP_1) T1(NC_3) T2(FIBRON_3) T3(FIBRIN_3) T4(RDN_3) T5(TDN_3) T6(FIBRON_2) T7(FIBRIN_2) T8(RDN_2) T9(TDN_2) T12(RDN_1) T13(TDN_1) T16(NC_4); Y3 2(NC)

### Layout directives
net class DP_50Ohms_TX: (no net found under the mark)
net class DP_50Ohms_RX_: (no net found under the mark)
differential pair; net class 100R_VS; differential pair class 100R_VS: _FIBRI0_N, _FIBRI0_P, _FIBRI1_N, _FIBRI1_P, _FIBRO0_N, _FIBRO0_P, _FIBRO1_N, _FIBRO1_P, _RD0_VS_N, _RD0_VS_P, _TD0_VS_N, _TD0_VS_P, FIBRI0_N, FIBRI0_P, FIBRI1_N, FIBRI1_P, FIBRO0_N, FIBRO0_P, FIBRO1_N, FIBRO1_P, RD0_VS_N, RD0_VS_P, REFCLK_N, REFCLK_P, TD0_VS_N, TD0_VS_P

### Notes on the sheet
- CRCW040259K0FKED
- Labels drawn without touching a wire or pin: 2V5_VSC

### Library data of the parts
C24-C26 C29 C655 C658-C660 = CMP-00621-81932632-1: CC0603KRX5R7BB106 Multilayer Ceramic Capacitor, 10 uF, 16 V, ± 10%, X5R, 0603 [1608 Metric]; Capacitance: 10µF; Voltage Rating: 16V
C27 C649 C650 C653 C656 C661 C663 C664 = CMP-03020-034679-1: CAP CER 1UF 16V X5R 0402; Dielectric Material: Ceramic; Tolerance: 10%
C28 C651 C652 C654 C657 C662 C665 C666 = CMP-03422-001280-2: CAP CER 0.1UF 25V X5R 0201
C186 C527 C602 = CMP-2000-06331-1: Chip Capacitor, 0.1 uF, +/- 10%, 10 V, -55 to 125 degC, 0402 (1005 Metric), RoHS, Tape and Reel; Manufacturer: Murata; Capacitance: 100000pF; Dielectric: X7R
C187 C528 C603 = CMP-08246-001970-1: Cap Ceramic 2.2nF 50V X7R 10% Pad SMD 0402 +125°C Automotive T/R
C188 C189 = CMP-03020-004605-1: CAP CER 10UF 25V X7R 1206 / C1206C106K3RACAUTO; Manufacturer: KEMET; Material: Ceramic; Automotive Grade: Grade 1; Temperature Coefficient: 15%; Tolerance: 10%
C202 C490 C522-C525 C531-C536 C620-C625 = CMP-1037-04994-1: CAP 22uF 16V -20% to +80% 1206 (3216 Metric) Thickness 1.9mm SMD; Case-Metric: 3216; Case-EIA: 1206
C526 C537 C626 = CMP-1036-04630-2: CAP CER 0.47UF 10V X7R 0805 / C0805C474J8RACTU; Manufacturer: KEMET; Value: 0.47 μF; Temperature Coefficient: 30ppm/°C; Tolerance: 0.05; Material: Ceramic
C529 C530 = CMP-06035-027412-1: Chip Multilayer Ceramic Capacitors for General Purpose, 1206, 22uF, X6S, 22%, 20%, 25V / GRM31CC81E226ME11K
C593-C596 C607-C610 C630 C631 C633 C634 = CMP-2008-03082-2: CAP CER 0.1UF 16V X7R 0402; Manufacturer Part Number: C0402C104K4RACAUTO; Manufacturer: Kemet; Temperature Coefficient: 15%; Tolerance: 0.1; Capacitance: 0.10 μF; Material: Ceramic; Value: 0.10 μF
C598 C599 C606 C618 = CMP-03020-010102-1: C0402 15 pF X8R 10.00% 50 V; Manufacturer Part Number: C0402C150K5HACAUTO; Manufacturer: Kemet; Tolerance: 0.1; Material: Ceramic; Temperature Coefficient: 15%; Capacitance: 15 pF; Voltage Rating: 50 V; Value: 15 pF
C604 C605 = CMP-08246-006695-1: Multilayer Ceramic Capacitors 6.8μF ±10% 35V X5R SMD 0805 / C2012X5R1V685K125AC; Capacitance: 6.8uF
C611 C627 = CMP-001-00074-3: 10uF 6.3V X5R ±20% 0402 Multilayer Ceramic Capacitors MLCC - SMD/SMT ROHS; Value: 10µF; Tolerance: 10%; MN: GRM155R60J106ME44D
C613 C614 = CMP-03422-000660-2: 1uF 6.3V X5R ±20% 0201 Multilayer Ceramic Capacitors MLCC - SMD/SMT ROHS; Manufacturer: Yageo; Manufacturer Part Number: CC0201MRX5R5BB105; Tolerance: 0.2; Temperature Coefficient: 15%; MN: CL03A105MQ3CSNH
C615-C617 C629 = CMP-2010-00672-2: Cap Ceramic 100nF 10V X5R ±10% Pad SMD 0201 +85°C T/R; MN: CL03A104KP3NNNC
C619 = CMP-2006-02217-1: Part Number: C0603C105M3RACTU; Manufacturer: Kemet
C628 = CMP-03422-000823-1: 10V 4.7uF X5R ±10% 0402 Multilayer Ceramic Capacitors MLCC - SMD/SMT ROHS; Manufacturer Part Number: CC0402KRX5R6BB475; Manufacturer: YAGEO; Automotive Grade: NA; Temperature Coefficient: 30ppm/°C; Tolerance: 0.1
C667 C668 C675 C676 = CMP-06035-005015-1: Chip Multilayer Ceramic Capacitors for General Purpose, 0805, 10uF, X5R, 15%, 10%, 50V / GRM21BR61H106KE43K
C669 C677 = CMP-2000-07546-2: Cap Ceramic 100nF 50V X7R 10% Pad SMD 0603 +125°C Automotive T/R / CGA3E2X7R1H104K080AA
C670 C678 = CMP-2008-03435-2: CAP CER 56PF 10V NP0 0402 / C0402C560J8GACTU; Manufacturer: Kemet; Material: Ceramic; Tolerance: 0.05; Temperature Characteristic: C0G; Temperature Coefficient: 15%
C671-C673 C679-C681 = CMP-06035-039918-1: Chip Multilayer Ceramic Capacitors for General Purpose, 0805, 22uF, X5R, 15%, 20%, 10V; Dissipation Factor: 0.035%
C674 C682 = CMP-1035-02595-8: Chip Multilayer Ceramic Capacitors for General Purpose, 0603, 0.10uF, X7R, 15%, 10%, 100V
L15 L24 L26 = CMP-03913-66963829-3: Inductor Power Shielded Wirewound 1uH 20% 100KHz Metal 10.1A 0.015Ohm DCR T/R Automotive AEC-Q200; Core Material: Composite, Metal; Current Rating: 7.2A; Self Resonant Frequency: 55MHz; Inductance: 1µH; Saturation Current: 9A; DC Resistance (DCR): 12mΩ
L27 L28 = CMP-2000-07144-1: Semi-Shielded Power Inductor, 2.2 uH, +/- 30%, 6.3 A, -40 to 125 degC, 2-Pin SMD, RoHS, Tape and Reel; Manufacturer: Bourns; Brand/Series: SRN8040Series; Current, Rating: 6.3A; Inductance: 2.2μH
P4 P5 = CMP-002-00034-2: Male Header, Pitch 2.5 mm, 1 x 4 Position, Height 6.1 mm, Tail Length 3.4 mm, -25 to 85 degC, RoHS, Bulk; Manufacturer: JST
R43 = CMP-2002-08310-2: RES Thick Film, 1.82kΩ, 1%, 0.063W, 100ppm/°C, 0402 / CRCW04021K82FKED; Voltage Rating (DC): 50V; Power Rating: 63mW; Tolerance: 5%; Resistance: 1.82kR
R50 R161 R232 = CMP-2002-03043-1: 10KR / CRCW040210K0FKEDHP; Manufacturer: Vishay Dale
R52 R162 R233 = CMP-2002-00056-2: RES Thick Film, 4.87kΩ, 1%, 0.063W, 100ppm/°C, 0402 / CRCW04024K87FKED; Voltage Rating: 50V; Resistance: 4.87kR; Max Power Dissipation: 63mW
R53 R163 = CMP-2002-08161-1: Resistance = 11.5 kΩ / Tolerance = 1.0% / Power = 63 mW / CRCW040211K5FKED; Manufacturer: Vishay Dale
R54 = CMP-26527-000161-1: 1.21kΩ ±1% 0.1W 0603 Thick Film Chip Resistor AEC-Q200 compliant / RMCF0603FG1K21; Max Power Dissipation: 100mW; Temperature Coefficient: 100ppm/°C; Resistance: 1.21kR
R187 = CMP-2002-06970-1: Part Number: RC0402JR-100RL; Manufacturer: Yageo
R189 R216-R227 R236-R241 R243-R246 = CMP-2002-06970-1: Manufacturer: Yageo
R215 R235 = CMP-03412-022181-1: RES SMD 11K OHM 0.1% 1/10W 0603; Manufacturer Part Number: RT0603BRC0711KL; Manufacturer: Yageo; Temperature Coefficient: 15 ppm/°C; Tolerance: 0.001; Value: 11KΩ; Voltage Rating: 75V; Power Rating: 0.1W
R228 R229 R249 R251 = CMP-1011-00293-2: Part Number: RC0402FR-0712R1L; Manufacturer: Yageo / Phycomp
R231 = CMP-2000-04117-2: RES 6.04K OHM 1% 1/10W 0603 / RC0603FR-076K04L; Temperature Coefficient: 100ppm/°C; Voltage Rating: 50V; Power Rating: 100mW; Resistance: 6.04kR
R234 = CMP-2002-08208-2: RES Thick Film, 14.3kΩ, 1%, 0.063W, 100ppm/°C, 0402 / CRCW040214K3FKED; Voltage Rating (DC): 50V; Max Power Dissipation: 63mW; Resistance: 14.3kR
R242 = CMP-03412-024188-2: RES 620Ω 1.00% 0.1W 0603; Max Power Dissipation: 100mW; Working Voltage: 75V; Voltage Rating: 50V; Tolerance: 1%; Temperature Coefficient: 100ppm/°C
R250 R252 R257 R259 R261 R262 = CMP-02407-008912-1: RES SMD 1.2K OHM 1% 1/10W 0402
R254 R268 = CMP-1011-00734-3: RES Thick Film, 95.3kΩ, 1%, 0.063W, 100ppm/°C, 0402 / CRCW040295K3FKED; Power Rating: 63mW; Voltage Rating (DC): 50V; Resistance: 95.3kR
R255 R269 = CMP-2002-08123-3: RES Thick Film, 100kΩ, 1%, 0.063W, 100ppm/°C, 0402 / CRCW0402100KFKED; Power Rating: 63mW; Resistance: 100kR; Voltage Rating (DC): 50V
R256 = CMP-03412-037842-1: RES 2kΩ 1.00% 0.1W 0603; Resistance: 2kR; Tolerance: 1%
R258 R260 = CMP-03412-001285-1: RES SMD 332 OHM 0.1% 1/10W 0603; Manufacturer Part Number: RT0603BRE07332RL; Manufacturer: Yageo; Voltage Rating: 75V; Tolerance: 0.001; Temperature Coefficient: 50 ppm/°C; Power Rating: 0.1W; Value: 332Ω
R266 R270 = CMP-02407-011830-1: 30K 0603 / MCT0603MC3002FP500
R267 R271 = CMP-2002-00113-1: CRCW040259K0FKED; Manufacturer: Vishay Dale
TP8 = CMP-00028-00002-2: 0.6mm round
U9 U48 U52 = PTPS62918RPYR: 17V VIN, 8A low-noise low-ripple buck converter with integrated ferrite-bead filter compensation 14-VQFN-HR -40 to 150; Manufacturer_Name: Texas Instruments
U47 U49 = CMP-04874-000002-2: IC TRANSCEIVER 1/1 48FN
U50 = CMP-06281-000140-1: IC TELECOM INTERFACE 256BGA; Number of Circuits: 1
U51 U53 = TPS565247DRLR
Y2 Y4 = CMP-27762-015150-1: Crystal 25MHz ±20ppm (Tol) ±100ppm (Stability) 12pF FUND 50Ω Automotive 4-Pin Ultra Mini-CSMD T/R; ESR (Equivalent Series Resistance): 50R
Y3 = CMP-06265-000025-1: MEMS OSC XO 125.0000MHZ LVDS SMD; Frequency Stability: 25ppm; Max Supply Current: 32mA; Min Supply Voltage: 2.25V; Max Supply Voltage: 3.6V; Frequency: 125MHz; Max Duty Cycle: 52%; Load Capacitance: 2pF

## Sheet Level_Shifter.SchDoc
size B; SheetNumber: 22; SheetTotal: 22
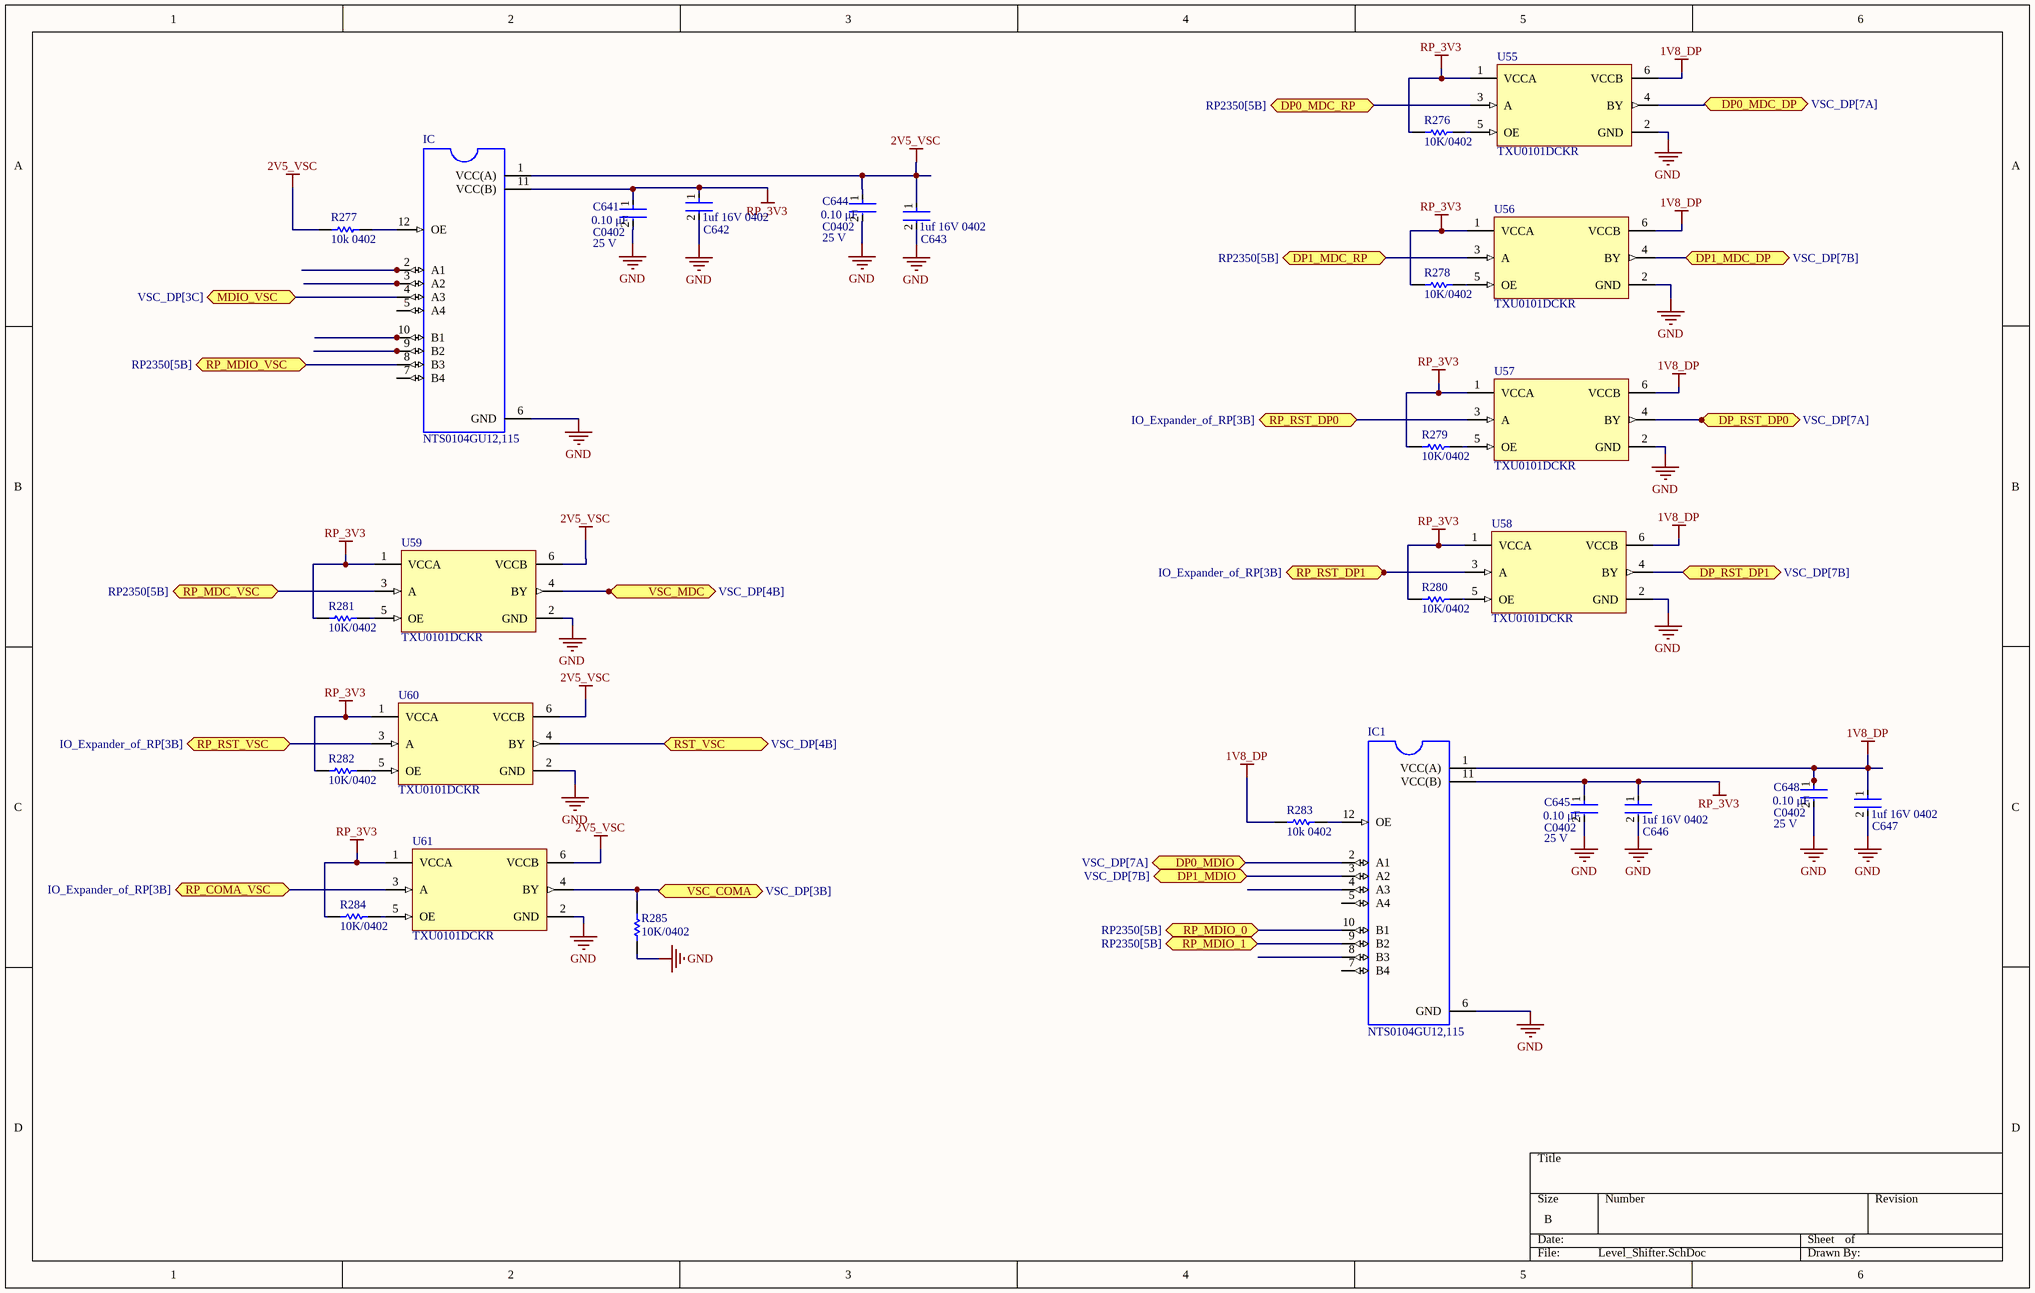
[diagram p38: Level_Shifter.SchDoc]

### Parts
C641  value 0.10 μF  Package: C0402  Voltage Rating: 25 V  [FP-C0402-BB-MFG]  (hidden comment: C0402C104M3PAC7867)
C642  1uf 16V 0402  [FP-CC0402-MFG]
C643  1uf 16V 0402  [FP-CC0402-MFG]
C644  value 0.10 μF  Package: C0402  Voltage Rating: 25 V  [FP-C0402-BB-MFG]  (hidden comment: C0402C104M3PAC7867)
C645  value 0.10 μF  Package: C0402  Voltage Rating: 25 V  [FP-C0402-BB-MFG]  (hidden comment: C0402C104M3PAC7867)
C646  1uf 16V 0402  [FP-CC0402-MFG]
C647  1uf 16V 0402  [FP-CC0402-MFG]
C648  value 0.10 μF  Package: C0402  Voltage Rating: 25 V  [FP-C0402-BB-MFG]  (hidden comment: C0402C104M3PAC7867)
IC  NTS0104GU12,115  [QFN40P170X200X50-12N]
IC1  NTS0104GU12,115  [QFN40P170X200X50-12N]
R276  10K/0402  [RESC1005X40X20NL05T10]
R277  10k 0402  [RESC1005X40X20NL05T10]
R278  10K/0402  [RESC1005X40X20NL05T10]
R279  10K/0402  [RESC1005X40X20NL05T10]
R280  10K/0402  [RESC1005X40X20NL05T10]
R281  10K/0402  [RESC1005X40X20NL05T10]
R282  10K/0402  [RESC1005X40X20NL05T10]
R283  10k 0402  [RESC1005X40X20NL05T10]
R284  10K/0402  [RESC1005X40X20NL05T10]
R285  10K/0402  [RESC1005X40X20NL05T10]
U55  TXU0101DCKR  [FP-DCK0006A-MFG]
U56  TXU0101DCKR  [FP-DCK0006A-MFG]
U57  TXU0101DCKR  [FP-DCK0006A-MFG]
U58  TXU0101DCKR  [FP-DCK0006A-MFG]
U59  TXU0101DCKR  [FP-DCK0006A-MFG]
U60  TXU0101DCKR  [FP-DCK0006A-MFG]
U61  TXU0101DCKR  [FP-DCK0006A-MFG]

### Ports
DP0_MDC_DP (bidir, see VSC_DP[7A]), DP0_MDC_RP (bidir, see RP2350[5B]), DP0_MDIO (bidir, see VSC_DP[7A]), DP1_MDC_DP (bidir, see VSC_DP[7B]), DP1_MDC_RP (bidir, see RP2350[5B]), DP1_MDIO (bidir, see VSC_DP[7B]), DP_RST_DP0 (bidir, see VSC_DP[7A]), DP_RST_DP1 (bidir, see VSC_DP[7B]), MDIO_VSC (bidir, see VSC_DP[3C]), RP_COMA_VSC (bidir, see IO_Expander_of_RP[3B]), RP_MDC_VSC (bidir, see RP2350[5B]), RP_MDIO_0 (bidir, see RP2350[5B]), RP_MDIO_1 (bidir, see RP2350[5B]), RP_MDIO_VSC (bidir, see RP2350[5B]), RP_RST_DP0 (bidir, see IO_Expander_of_RP[3B]), RP_RST_DP1 (bidir, see IO_Expander_of_RP[3B]), RP_RST_VSC (bidir, see IO_Expander_of_RP[3B]), RST_VSC (bidir, see VSC_DP[4B]), VSC_COMA (bidir, see VSC_DP[3B]), VSC_MDC (bidir, see VSC_DP[4B])

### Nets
1V8_DP: C647.1 C648.1 IC1.1(VCC(A)) R283.1 U55.6(VCCB) U56.6(VCCB) U57.6(VCCB) U58.6(VCCB)
2V5_VSC: C643.1 C644.1 IC.1(VCC(A)) R277.1 U59.6(VCCB) U60.6(VCCB) U61.6(VCCB)
GND: C641.2 C642.2 C643.2 C644.2 C645.2 C646.2 C647.2 C648.2 IC.6(GND) IC1.6(GND) R285.2 U55.2(GND) U56.2(GND) U57.2(GND) U58.2(GND) U59.2(GND) U60.2(GND) U61.2(GND)
RP_3V3: C641.1 C642.1 C645.1 C646.1 IC.11(VCC(B)) IC1.11(VCC(B)) R276.2 R278.2 R279.2 R280.2 R281.2 R282.2 R284.2 U55.1(VCCA) U56.1(VCCA) U57.1(VCCA) U58.1(VCCA) U59.1(VCCA) U60.1(VCCA) U61.1(VCCA)  [project net 3V3]
DP0_MDC_DP: U55.4(BY) ; port DP0_MDC_DP
DP0_MDC_RP: U55.3(A) ; port DP0_MDC_RP
DP0_MDIO: IC1.2(A1) ; port DP0_MDIO
DP1_MDC_DP: U56.4(BY) ; port DP1_MDC_DP
DP1_MDC_RP: U56.3(A) ; port DP1_MDC_RP
DP1_MDIO: IC1.3(A2) ; port DP1_MDIO
DP_RST_DP0: U57.4(BY) ; port DP_RST_DP0
DP_RST_DP1: U58.4(BY) ; port DP_RST_DP1
MDIO_VSC: IC.4(A3) ; port MDIO_VSC
RP_COMA_VSC: U61.3(A) ; port RP_COMA_VSC
RP_MDC_VSC: U59.3(A) ; port RP_MDC_VSC
RP_MDIO_0: IC1.10(B1) ; port RP_MDIO_0
RP_MDIO_1: IC1.9(B2) ; port RP_MDIO_1
RP_MDIO_VSC: IC.8(B3) ; port RP_MDIO_VSC
RP_RST_DP0: U57.3(A) ; port RP_RST_DP0
RP_RST_DP1: U58.3(A) ; port RP_RST_DP1
RP_RST_VSC: U60.3(A) ; port RP_RST_VSC
RST_VSC: U60.4(BY) ; port RST_VSC
VSC_COMA: R285.1 U61.4(BY) ; port VSC_COMA
VSC_MDC: U59.4(BY) ; port VSC_MDC
NetIC1_12: IC1.12(OE) R283.2
NetIC_12: IC.12(OE) R277.2
NetR276_1: R276.1 U55.5(OE)
NetR278_1: R278.1 U56.5(OE)
NetR279_1: R279.1 U57.5(OE)
NetR280_1: R280.1 U58.5(OE)
NetR281_1: R281.1 U59.5(OE)
NetR282_1: R282.1 U60.5(OE)
NetR284_1: R284.1 U61.5(OE)

Not connected (* = marked no-connect by the designer): IC 2(A1) 3(A2) 5(A4) 7(B4) 9(B2) 10(B1); IC1 4(A3) 5(A4) 7(B4) 8(B3)

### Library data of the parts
C641 C644 C645 C648 = CMP-03020-014070-2: CAP CER 0.1UF 25V X5R 0402; Manufacturer: Kemet; Material: Ceramic; Tolerance: 0.2; Temperature Coefficient: 15%
C642 C643 C646 C647 = CMP-03422-000114-1: CAP CER 1UF 25V X5R 0402; Manufacturer Part Number: CC0402KRX5R8BB105; Manufacturer: YAGEO; Automotive Grade: NA; Tolerance: 0.1; Material: Ceramic; Temperature Coefficient: 30ppm/°C
IC IC1 = NTS0104GU12,115: Voltage Level Translator Bidirectional 1 Circuit 4 Channel 50Mbps 12-XQFN _2x1.7_; MF: NXP USA
R276 R278-R282 R284 R285 = CMP-2002-01682-1: Manufacturer: Vishay BCcomponents; Part Number: TNPW040210K0DEED
R277 R283 = CMP-2002-01682-1: TNPW040210K0DEED; Manufacturer: Vishay BCcomponents
U55-U61 = CMP-00370-128857311-1: Single channel fixed-direction level shifter 6-SC70 -40 to 125; Manufacturer Lifecycle Status: ACTIVE; Number of Inputs: 1; Propagation Delay: 69ns; Max Junction Temperature (Tj): 150°C; Data Rate: 200Mbps; Nominal Supply Current: 2.5µA

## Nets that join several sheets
0V9: LAN9696_Supply (52 pins), LAN_Supply (10 pins)
1V1: 8841 (11 pins), VSC_DP (22 pins)
1V2: LAN9696_Supply (21 pins), LAN_Supply (5 pins)
1V8: SPI _NOR (R72.2 R73.2 U7.8), LAN9696 (25 pins), LAN9696_Supply (40 pins), LAN_Supply (10 pins), 8841 (20 pins)
1V8_DP: VSC_DP (30 pins), Level_Shifter (8 pins)
2V5_VSC: VSC_DP (29 pins), Level_Shifter (7 pins)
3V3: rk3588 (5 pins), LAN9696 (14 pins), LAN_Supply (8 pins), 8841 (FB25.1 R398.2 R401.2), RP2350 (28 pins), IO_Expander_of_RP (9 pins), VSC_DP (Y3.1 Y3.6), Level_Shifter (20 pins)
5V: LAN_Supply (22 pins), VSC_DP (16 pins)
12V: LAN_Supply (16 pins), BoardSupply (15 pins), VSC_DP (12 pins)
+24V: BoardSupply (10 pins), IO_Expander_of_RP (14 pins)
EMMC_VCC: rk3588 (C23.1 R301.2 R304.2 U3.P28), RK806-1 (5 pins), ATE_Safety (U6.8), EMMC (8 pins), Discrete Power (5 pins), RS232 DBG_UART (C543.1 C544.2 U8.4)
GND: rk3588 (59 pins), RK3588_Power (451 pins), rk3588_LPDDR4 (32 pins), RK806-1 (71 pins), ATE_Safety (U6.4), SPI _NOR (U7.4), LAN9696 (39 pins), LAN9696_Supply (160 pins), LAN_Supply (65 pins), 8841 (37 pins), EMMC (20 pins), LPDDR4_EDA (200 pins), BoardSupply (43 pins), RK3588_USB2.0_USB3.0 (17 pins), HDMI (31 pins), Discrete Power (59 pins), RS232 DBG_UART (21 pins), Key Array (25 pins), RP2350 (44 pins), IO_Expander_of_RP (42 pins), VSC_DP (194 pins), Level_Shifter (18 pins)
NLDO1: rk3588 (TP2.1 U3.P27), RK806-1 (C168.1 U5.14)
NLDO2: rk3588_LPDDR4 (5 pins), RK806-1 (C169.1 TP28.1 U5.12)
NLDO3: RK806-1 (C171.1 TP29.1 U5.11), HDMI (5 pins)
NLDO4: RK806-1 (C172.1 TP27.1 U5.10), RK3588_USB2.0_USB3.0 (C459.2 C460.1 U3.AH14 U3.AJ14)
NLDO5: rk3588 (C17.2 U3.AD3 U3.V20), RK806-1 (C167.1 U5.8), RK3588_USB2.0_USB3.0 (C454.1 TP67.1 U3.AH10), HDMI (C471.2 U3.AE8)
PLDO4: RK806-1 (C177.2 TP35.1 U5.63), BoardSupply (C434.1 R75.2 U18.12), RK3588_USB2.0_USB3.0 (C456.1 U3.AJ10), HDMI (C472.2 C473.1 U3.AE4 U3.AE5)
PLDO5: rk3588 (C612.1 U3.Y7), RK806-1 (C178.2 U5.65)
VCC1: RK806-1 (30 pins), BoardSupply (9 pins), Discrete Power (21 pins)
VCC1V8_PMU_DDR_S3: rk3588 (C5.1 U3.N28 U3.R27 U54.6), RK806-1 (R30.1 R31.1 TP18.1), LPDDR4_EDA (36 pins)
VCC14: RK806-1 (C176.2 TP38.1 U5.9), Discrete Power (6 pins)
VCC_1V8_S0: rk3588 (12 pins), RK806-1 (C556.2 U5.58), HDMI (7 pins), Discrete Power (R133.2)
VCC_3V3_S0: rk3588 (C204.1 J5.2 U3.AC26), HDMI (5 pins), Discrete Power (5.2 U26.1), RS232 DBG_UART (C547.1 U32.16)
VCC_5V0: BoardSupply (9 pins), HDMI (D4.2 D7.1 Q12.1)
VCCA_1V8: rk3588 (10 pins), rk3588_LPDDR4 (5 pins), RK806-1 (C555.2 U5.60), RK3588_USB2.0_USB3.0 (5 pins)
VCCQ: RK806-1 (8 pins), EMMC (17 pins)
VDD2_DDR_CKE: rk3588_LPDDR4 (5 pins), LPDDR4_EDA (R264.1)
VDD_CPU_BIG0_S0: RK3588_Power (25 pins), Discrete Power (5 pins)
VDD_CPU_BIG1_MEM_S0: RK3588_Power (U3.M21 U3.N21), Discrete Power (C508.1 FB9.2)
VDD_CPU_BIG1_S0: RK3588_Power (21 pins), Discrete Power (6 pins)
VDD_CPU_LIT_S0: RK3588_Power (20 pins), RK806-1 (6 pins)
VDD_DDR_S0: rk3588_LPDDR4 (23 pins), RK806-1 (6 pins)
VDD_GPU_S0: RK3588_Power (25 pins), RK806-1 (C350.1 R247.2 R248.2)
VDD_LOG_S0: RK3588_Power (20 pins), RK806-1 (6 pins)
VDD_NPU_S0: RK3588_Power (18 pins), Discrete Power (5 pins)
VDD_VDENC_S0: RK3588_Power (18 pins), RK806-1 (6 pins)
VDDQ_DDR_CK: rk3588_LPDDR4 (5 pins), LPDDR4_EDA (R265.1)
VOUT6: RK806-1 (8 pins), LPDDR4_EDA (83 pins)
VOUT9: rk3588_LPDDR4 (27 pins), RK806-1 (7 pins), LPDDR4_EDA (R263.2 R265.2)
BOOT_SARADC_IN0: rk3588 (IC2.10), IO_Expander_of_RP (U43.23)
BOOT_SARADC_IN0_: rk3588 (IC2.2 J10.7 R130.2 U3.AM16), Key Array (R183.1)
CLK125EN: LAN9696 (U1.G19), 8841 (R396.2 U45.34)
CPU_BIG0_VSEL: rk3588 (U3.R31), Discrete Power (U23.A1)
CPU_BIG1_VSEL: rk3588 (U3.W28), Discrete Power (U22.A1)
DDR_CH0_A0_A: rk3588_LPDDR4 (U3.T7), LPDDR4_EDA (U15.H2)
DDR_CH0_A0_B: rk3588_LPDDR4 (U3.M8), LPDDR4_EDA (U15.R2)
DDR_CH0_A1_A: rk3588_LPDDR4 (U3.T8), LPDDR4_EDA (U15.J2)
DDR_CH0_A1_B: rk3588_LPDDR4 (U3.M5), LPDDR4_EDA (U15.P2)
DDR_CH0_A2_A: rk3588_LPDDR4 (U3.P4), LPDDR4_EDA (U15.H9)
DDR_CH0_A2_B: rk3588_LPDDR4 (U3.N5), LPDDR4_EDA (U15.R9)
DDR_CH0_A3_A: rk3588_LPDDR4 (U3.P5), LPDDR4_EDA (U15.H10)
DDR_CH0_A3_B: rk3588_LPDDR4 (U3.N4), LPDDR4_EDA (U15.R10)
DDR_CH0_A4_A: rk3588_LPDDR4 (U3.R1), LPDDR4_EDA (U15.H11)
DDR_CH0_A4_B: rk3588_LPDDR4 (U3.K1), LPDDR4_EDA (U15.R11)
DDR_CH0_A5_A: rk3588_LPDDR4 (U3.P2), LPDDR4_EDA (U15.J11)
DDR_CH0_A5_B: rk3588_LPDDR4 (U3.L2), LPDDR4_EDA (U15.P11)
DDR_CH0_CLK_A_N: rk3588_LPDDR4 (U3.N1), LPDDR4_EDA (U15.J9)
DDR_CH0_CLK_A_P: rk3588_LPDDR4 (U3.N2), LPDDR4_EDA (U15.J8)
DDR_CH0_CLK_B_N: rk3588_LPDDR4 (U3.M1), LPDDR4_EDA (U15.P9)
DDR_CH0_CLK_B_P: rk3588_LPDDR4 (U3.M2), LPDDR4_EDA (U15.P8)
DDR_CH0_DM0_A: rk3588_LPDDR4 (U3.Y4), LPDDR4_EDA (U15.C3)
DDR_CH0_DM0_B: rk3588_LPDDR4 (U3.G4), LPDDR4_EDA (U15.Y3)
DDR_CH0_DM1_A: rk3588_LPDDR4 (U3.AB4), LPDDR4_EDA (U15.C10)
DDR_CH0_DM1_B: rk3588_LPDDR4 (U3.E4), LPDDR4_EDA (U15.Y10)
DDR_CH0_DQ0_A: rk3588_LPDDR4 (U3.U1), LPDDR4_EDA (U15.B2)
DDR_CH0_DQ0_B: rk3588_LPDDR4 (U3.H1), LPDDR4_EDA (U15.AA2)
DDR_CH0_DQ1_A: rk3588_LPDDR4 (U3.T2), LPDDR4_EDA (U15.C2)
DDR_CH0_DQ1_B: rk3588_LPDDR4 (U3.J2), LPDDR4_EDA (U15.Y2)
DDR_CH0_DQ2_A: rk3588_LPDDR4 (U3.T1), LPDDR4_EDA (U15.E2)
DDR_CH0_DQ2_B: rk3588_LPDDR4 (U3.J1), LPDDR4_EDA (U15.V2)
DDR_CH0_DQ3_A: rk3588_LPDDR4 (U3.R2), LPDDR4_EDA (U15.F2)
DDR_CH0_DQ3_B: rk3588_LPDDR4 (U3.K2), LPDDR4_EDA (U15.U2)
DDR_CH0_DQ4_A: rk3588_LPDDR4 (U3.W1), LPDDR4_EDA (U15.F4)
DDR_CH0_DQ4_B: rk3588_LPDDR4 (U3.F1), LPDDR4_EDA (U15.U4)
DDR_CH0_DQ5_A: rk3588_LPDDR4 (U3.V2), LPDDR4_EDA (U15.E4)
DDR_CH0_DQ5_B: rk3588_LPDDR4 (U3.G2), LPDDR4_EDA (U15.V4)
DDR_CH0_DQ6_A: rk3588_LPDDR4 (U3.V1), LPDDR4_EDA (U15.C4)
DDR_CH0_DQ6_B: rk3588_LPDDR4 (U3.G1), LPDDR4_EDA (U15.Y4)
DDR_CH0_DQ7_A: rk3588_LPDDR4 (U3.U2), LPDDR4_EDA (U15.B4)
DDR_CH0_DQ7_B: rk3588_LPDDR4 (U3.H2), LPDDR4_EDA (U15.AA4)
DDR_CH0_DQ8_A: rk3588_LPDDR4 (U3.AB2), LPDDR4_EDA (U15.B11)
DDR_CH0_DQ8_B: rk3588_LPDDR4 (U3.D2), LPDDR4_EDA (U15.AA11)
DDR_CH0_DQ9_A: rk3588_LPDDR4 (U3.AB1), LPDDR4_EDA (U15.C11)
DDR_CH0_DQ9_B: rk3588_LPDDR4 (U3.C1), LPDDR4_EDA (U15.Y11)
DDR_CH0_DQ10_A: rk3588_LPDDR4 (U3.AC1), LPDDR4_EDA (U15.E11)
DDR_CH0_DQ10_B: rk3588_LPDDR4 (U3.C2), LPDDR4_EDA (U15.V11)
DDR_CH0_DQ11_A: rk3588_LPDDR4 (U3.AC2), LPDDR4_EDA (U15.F11)
DDR_CH0_DQ11_B: rk3588_LPDDR4 (U3.B1), LPDDR4_EDA (U15.U11)
DDR_CH0_DQ12_A: rk3588_LPDDR4 (U3.Y1), LPDDR4_EDA (U15.F9)
DDR_CH0_DQ12_B: rk3588_LPDDR4 (U3.F2), LPDDR4_EDA (U15.U9)
DDR_CH0_DQ13_A: rk3588_LPDDR4 (U3.Y2), LPDDR4_EDA (U15.E9)
DDR_CH0_DQ13_B: rk3588_LPDDR4 (U3.E1), LPDDR4_EDA (U15.V9)
DDR_CH0_DQ14_A: rk3588_LPDDR4 (U3.AA1), LPDDR4_EDA (U15.C9)
DDR_CH0_DQ14_B: rk3588_LPDDR4 (U3.E2), LPDDR4_EDA (U15.Y9)
DDR_CH0_DQ15_A: rk3588_LPDDR4 (U3.AA2), LPDDR4_EDA (U15.B9)
DDR_CH0_DQ15_B: rk3588_LPDDR4 (U3.D1), LPDDR4_EDA (U15.AA9)
DDR_CH0_DQS0_A_N: rk3588_LPDDR4 (U3.U4), LPDDR4_EDA (U15.E3)
DDR_CH0_DQS0_A_P: rk3588_LPDDR4 (U3.U5), LPDDR4_EDA (U15.D3)
DDR_CH0_DQS0_B_N: rk3588_LPDDR4 (U3.J7), LPDDR4_EDA (U15.V3)
DDR_CH0_DQS0_B_P: rk3588_LPDDR4 (U3.J8), LPDDR4_EDA (U15.W3)
DDR_CH0_DQS1_A_N: rk3588_LPDDR4 (U3.AA4), LPDDR4_EDA (U15.E10)
DDR_CH0_DQS1_A_P: rk3588_LPDDR4 (U3.AA5), LPDDR4_EDA (U15.D10)
DDR_CH0_DQS1_B_N: rk3588_LPDDR4 (U3.F4), LPDDR4_EDA (U15.V10)
DDR_CH0_DQS1_B_P: rk3588_LPDDR4 (U3.F5), LPDDR4_EDA (U15.W10)
DDR_CH0_LP4/4X_CKE0/LP5_CS0_A: rk3588_LPDDR4 (U3.P7), LPDDR4_EDA (R27.1)
DDR_CH0_LP4/4X_CKE0/LP5_CS0_B: rk3588_LPDDR4 (U3.L5), LPDDR4_EDA (R151.1)
DDR_CH0_LP4/4X_CKE1/LP5_CS1_A: rk3588_LPDDR4 (U3.N7), LPDDR4_EDA (R150.1)
DDR_CH0_LP4/4X_CKE1/LP5_CS1_B: rk3588_LPDDR4 (U3.L4), LPDDR4_EDA (R152.1)
DDR_CH0_LP4/4X_CS0_A: rk3588_LPDDR4 (U3.R6), LPDDR4_EDA (U15.H4)
DDR_CH0_LP4/4X_CS0_B: rk3588_LPDDR4 (U3.L7), LPDDR4_EDA (U15.R4)
DDR_CH0_LP4/4X_CS1_A: rk3588_LPDDR4 (U3.R7), LPDDR4_EDA (U15.H3)
DDR_CH0_LP4/4X_CS1_B: rk3588_LPDDR4 (U3.L8), LPDDR4_EDA (U15.R3)
DDR_CH1_A0_C: rk3588_LPDDR4 (U3.G12), LPDDR4_EDA (U12.H2)
DDR_CH1_A0_D: rk3588_LPDDR4 (U3.H15), LPDDR4_EDA (U12.R2)
DDR_CH1_A1_C: rk3588_LPDDR4 (U3.F12), LPDDR4_EDA (U12.J2)
DDR_CH1_A1_D: rk3588_LPDDR4 (U3.G14), LPDDR4_EDA (U12.P2)
DDR_CH1_A2_C: rk3588_LPDDR4 (U3.E13), LPDDR4_EDA (U12.H9)
DDR_CH1_A2_D: rk3588_LPDDR4 (U3.G13), LPDDR4_EDA (U12.R9)
DDR_CH1_A3_C: rk3588_LPDDR4 (U3.D13), LPDDR4_EDA (U12.H10)
DDR_CH1_A3_D: rk3588_LPDDR4 (U3.E14), LPDDR4_EDA (U12.R10)
DDR_CH1_A4_C: rk3588_LPDDR4 (U3.A10), LPDDR4_EDA (U12.H11)
DDR_CH1_A4_D: rk3588_LPDDR4 (U3.A15), LPDDR4_EDA (U12.R11)
DDR_CH1_A5_C: rk3588_LPDDR4 (U3.B11), LPDDR4_EDA (U12.J11)
DDR_CH1_A5_D: rk3588_LPDDR4 (U3.B14), LPDDR4_EDA (U12.P11)
DDR_CH1_CLK_C_N: rk3588_LPDDR4 (U3.A12), LPDDR4_EDA (U12.J9)
DDR_CH1_CLK_C_P: rk3588_LPDDR4 (U3.B12), LPDDR4_EDA (U12.J8)
DDR_CH1_CLK_D_N: rk3588_LPDDR4 (U3.A13), LPDDR4_EDA (U12.P9)
DDR_CH1_CLK_D_P: rk3588_LPDDR4 (U3.B13), LPDDR4_EDA (U12.P8)
DDR_CH1_DM0_C: rk3588_LPDDR4 (U3.F8), LPDDR4_EDA (U12.C3)
DDR_CH1_DM0_D: rk3588_LPDDR4 (U3.D20), LPDDR4_EDA (U12.Y3)
DDR_CH1_DM1_C: rk3588_LPDDR4 (U3.D4), LPDDR4_EDA (U12.C10)
DDR_CH1_DM1_D: rk3588_LPDDR4 (U3.D22), LPDDR4_EDA (U12.Y10)
DDR_CH1_DQ0_C: rk3588_LPDDR4 (U3.A8), LPDDR4_EDA (U12.B2)
DDR_CH1_DQ0_D: rk3588_LPDDR4 (U3.A17), LPDDR4_EDA (U12.AA2)
DDR_CH1_DQ1_C: rk3588_LPDDR4 (U3.B9), LPDDR4_EDA (U12.C2)
DDR_CH1_DQ1_D: rk3588_LPDDR4 (U3.B16), LPDDR4_EDA (U12.Y2)
DDR_CH1_DQ2_C: rk3588_LPDDR4 (U3.A9), LPDDR4_EDA (U12.E2)
DDR_CH1_DQ2_D: rk3588_LPDDR4 (U3.A16), LPDDR4_EDA (U12.V2)
DDR_CH1_DQ3_C: rk3588_LPDDR4 (U3.B10), LPDDR4_EDA (U12.F2)
DDR_CH1_DQ3_D: rk3588_LPDDR4 (U3.B15), LPDDR4_EDA (U12.U2)
DDR_CH1_DQ4_C: rk3588_LPDDR4 (U3.A6), LPDDR4_EDA (U12.F4)
DDR_CH1_DQ4_D: rk3588_LPDDR4 (U3.A19), LPDDR4_EDA (U12.U4)
DDR_CH1_DQ5_C: rk3588_LPDDR4 (U3.B7), LPDDR4_EDA (U12.E4)
DDR_CH1_DQ5_D: rk3588_LPDDR4 (U3.B18), LPDDR4_EDA (U12.V4)
DDR_CH1_DQ6_C: rk3588_LPDDR4 (U3.A7), LPDDR4_EDA (U12.C4)
DDR_CH1_DQ6_D: rk3588_LPDDR4 (U3.A18), LPDDR4_EDA (U12.Y4)
DDR_CH1_DQ7_C: rk3588_LPDDR4 (U3.B8), LPDDR4_EDA (U12.B4)
DDR_CH1_DQ7_D: rk3588_LPDDR4 (U3.B17), LPDDR4_EDA (U12.AA4)
DDR_CH1_DQ8_C: rk3588_LPDDR4 (U3.A3), LPDDR4_EDA (U12.B11)
DDR_CH1_DQ8_D: rk3588_LPDDR4 (U3.A22), LPDDR4_EDA (U12.AA11)
DDR_CH1_DQ9_C: rk3588_LPDDR4 (U3.B3), LPDDR4_EDA (U12.C11)
DDR_CH1_DQ9_D: rk3588_LPDDR4 (U3.B22), LPDDR4_EDA (U12.Y11)
DDR_CH1_DQ10_C: rk3588_LPDDR4 (U3.A2), LPDDR4_EDA (U12.E11)
DDR_CH1_DQ10_D: rk3588_LPDDR4 (U3.A23), LPDDR4_EDA (U12.V11)
DDR_CH1_DQ11_C: rk3588_LPDDR4 (U3.B2), LPDDR4_EDA (U12.F11)
DDR_CH1_DQ11_D: rk3588_LPDDR4 (U3.B23), LPDDR4_EDA (U12.U11)
DDR_CH1_DQ12_C: rk3588_LPDDR4 (U3.A5), LPDDR4_EDA (U12.F9)
DDR_CH1_DQ12_D: rk3588_LPDDR4 (U3.A20), LPDDR4_EDA (U12.U9)
DDR_CH1_DQ13_C: rk3588_LPDDR4 (U3.B5), LPDDR4_EDA (U12.E9)
DDR_CH1_DQ13_D: rk3588_LPDDR4 (U3.B20), LPDDR4_EDA (U12.V9)
DDR_CH1_DQ14_C: rk3588_LPDDR4 (U3.A4), LPDDR4_EDA (U12.C9)
DDR_CH1_DQ14_D: rk3588_LPDDR4 (U3.A21), LPDDR4_EDA (U12.Y9)
DDR_CH1_DQ15_C: rk3588_LPDDR4 (U3.B4), LPDDR4_EDA (U12.B9)
DDR_CH1_DQ15_D: rk3588_LPDDR4 (U3.B21), LPDDR4_EDA (U12.AA9)
DDR_CH1_DQS0_C_N: rk3588_LPDDR4 (U3.D9), LPDDR4_EDA (U12.E3)
DDR_CH1_DQS0_C_P: rk3588_LPDDR4 (U3.E9), LPDDR4_EDA (U12.D3)
DDR_CH1_DQS0_D_N: rk3588_LPDDR4 (U3.G16), LPDDR4_EDA (U12.V3)
DDR_CH1_DQS0_D_P: rk3588_LPDDR4 (U3.H16), LPDDR4_EDA (U12.W3)
DDR_CH1_DQS1_C_N: rk3588_LPDDR4 (U3.D5), LPDDR4_EDA (U12.E10)
DDR_CH1_DQS1_C_P: rk3588_LPDDR4 (U3.E5), LPDDR4_EDA (U12.D10)
DDR_CH1_DQS1_D_N: rk3588_LPDDR4 (U3.E21), LPDDR4_EDA (U12.V10)
DDR_CH1_DQS1_D_P: rk3588_LPDDR4 (U3.D21), LPDDR4_EDA (U12.W10)
DDR_CH1_LP4/4X_CKE0/LP5_CS0_C: rk3588_LPDDR4 (U3.D11), LPDDR4_EDA (R153.1)
DDR_CH1_LP4/4X_CKE0/LP5_CS0_D: rk3588_LPDDR4 (U3.D16), LPDDR4_EDA (R155.1)
DDR_CH1_LP4/4X_CKE1/LP5_CS1_C: rk3588_LPDDR4 (U3.E11), LPDDR4_EDA (R154.1)
DDR_CH1_LP4/4X_CKE1/LP5_CS1_D: rk3588_LPDDR4 (U3.E16), LPDDR4_EDA (R156.1)
DDR_CH1_LP4/4X_CS0_C: rk3588_LPDDR4 (U3.G11), LPDDR4_EDA (U12.H4)
DDR_CH1_LP4/4X_CS0_D: rk3588_LPDDR4 (U3.E19), LPDDR4_EDA (U12.R4)
DDR_CH1_LP4/4X_CS1_C: rk3588_LPDDR4 (U3.H11), LPDDR4_EDA (U12.H3)
DDR_CH1_LP4/4X_CS1_D: rk3588_LPDDR4 (U3.D19), LPDDR4_EDA (U12.R3)
DDR_RESET: rk3588_LPDDR4 (U3.T4), LPDDR4_EDA (U15.T11)
DP0_MDC_DP: VSC_DP (U47.42), Level_Shifter (U55.4)
DP0_MDC_RP: RP2350 (U35.12), Level_Shifter (U55.3)
DP0_MDIO: VSC_DP (U47.41), Level_Shifter (IC1.2)
DP1_MDC_DP: VSC_DP (U49.42), Level_Shifter (U56.4)
DP1_MDC_RP: RP2350 (U35.13), Level_Shifter (U56.3)
DP1_MDIO: VSC_DP (U49.41), Level_Shifter (IC1.3)
DP_RST_DP0: VSC_DP (U47.43), Level_Shifter (U57.4)
DP_RST_DP1: VSC_DP (U49.43), Level_Shifter (U58.4)
FSPI_CLK_M0: rk3588 (U3.AM29), SPI _NOR (U7.6)
FSPI_CS0N_M0: rk3588 (U3.AK25), SPI _NOR (U7.1)
FSPI_D0_M0: rk3588 (U3.AK30), SPI _NOR (U7.2)
FSPI_D1_M0: rk3588 (U3.AL30), SPI _NOR (U7.5)
GMAC0_RXCLK: rk3588 (U3.AE32), VSC_DP (R222.1)
GMAC0_RXD0: rk3588 (U3.AD32), VSC_DP (R224.1)
GMAC0_RXD1: rk3588 (U3.AD31), VSC_DP (R225.1)
GMAC0_RXD2: rk3588 (U3.AC32), VSC_DP (R226.1)
GMAC0_RXD3: rk3588 (U3.AC31), VSC_DP (R227.1)
GMAC0_RXDV_CRS: rk3588 (U3.AE31), VSC_DP (R223.1)
GMAC0_TXCLK: rk3588 (U3.AE33), VSC_DP (R216.1)
GMAC0_TXD0: rk3588 (U3.AD33), VSC_DP (R218.1)
GMAC0_TXD1: rk3588 (U3.AD34), VSC_DP (R219.1)
GMAC0_TXD2: rk3588 (U3.AC33), VSC_DP (R187.1)
GMAC0_TXD3: rk3588 (U3.AC34), VSC_DP (R221.1)
GMAC0_TXEN: rk3588 (U3.AE34), VSC_DP (R217.1)
GMAC1_RXCLK: rk3588 (U3.AH30), VSC_DP (R240.1)
GMAC1_RXD0: rk3588 (U3.AG29), VSC_DP (R243.1)
GMAC1_RXD1: rk3588 (U3.AG28), VSC_DP (R244.1)
GMAC1_RXD2: rk3588 (U3.AD27), VSC_DP (R245.1)
GMAC1_RXD3: rk3588 (U3.AE27), VSC_DP (R246.1)
GMAC1_RXDV_CRS: rk3588 (U3.AH29), VSC_DP (R241.1)
GMAC1_TXCLK: rk3588 (U3.AD28), VSC_DP (R189.1)
GMAC1_TXD0: rk3588 (U3.AC28), VSC_DP (R236.1)
GMAC1_TXD1: rk3588 (U3.AC29), VSC_DP (R237.1)
GMAC1_TXD2: rk3588 (U3.AA29), VSC_DP (R238.1)
GMAC1_TXD3: rk3588 (U3.AA30), VSC_DP (R239.1)
GMAC1_TXEN: rk3588 (U3.AD29), VSC_DP (R220.1)
HDMITX0_CEC_M0: rk3588 (U3.AK24), HDMI (Q12.2 R119.1)
HDMITX0_HPDIN_M0: rk3588 (U3.B26), HDMI (Q4.3 R100.1)
HDMITX0_SCL_M0: rk3588 (U3.AJ28), HDMI (Q6.2 R107.2)
HDMITX0_SDA_M0: rk3588 (U3.AJ25), HDMI (C482.1 Q11.2 R114.2)
I2C0_SCL_M2: rk3588 (U3.W30), Discrete Power (U22.A3 U23.A3)
I2C0_SDA_M2: rk3588 (U3.W29), Discrete Power (U22.B1 U23.B1)
I2C1_SCL_M2: rk3588 (U3.V29), Discrete Power (U24.A3)
I2C1_SDA_M2: rk3588 (U3.V28), Discrete Power (U24.B1)
I2C6_SCL_M0: rk3588 (R301.1 U3.W31), ATE_Safety (U6.6)
I2C6_SDA_M0: rk3588 (R304.1 U3.V31), ATE_Safety (U6.5)
LCD_PWREN_H: rk3588 (U3.U33), Discrete Power (R135.1 U27.4)
MDC: LAN9696 (U1.B3), 8841 (U45.37)
MDIO: LAN9696 (U1.C1), 8841 (U45.38)
MDIO_VSC: VSC_DP (U50.N2), Level_Shifter (IC.4)
MODE0: LAN9696 (U1.J19), 8841 (R385.1 R386.2 U45.33)
MODE1: LAN9696 (U1.J18), 8841 (R383.1 R384.2 U45.32)
MODE2: LAN9696 (U1.H19), 8841 (R381.1 R382.2 U45.30)
MODE3: LAN9696 (U1.H18), 8841 (R376.1 R377.2 U45.29)
MODE4: LAN9696 (U1.H17), 8841 (R374.1 R375.2 U45.36)
NPU_VSEL: rk3588 (U3.U32), Discrete Power (U24.A1)
PMIC_EXT_EN_OUT: RK806-1 (U5.39), Discrete Power (R127.2)
PMIC_INT_L: rk3588 (U3.M30), RK806-1 (R41.1 U5.19)
PMIC_PWR_CTRL1: rk3588 (U3.R32), RK806-1 (U5.62)
PMIC_PWR_CTRL2: rk3588 (R3.1 R20.2), RK806-1 (U5.61)
PMIC_SPI_CLK: rk3588 (R24.2), RK806-1 (U5.17)
PMIC_SPI_CS: rk3588 (U3.K30), RK806-1 (U5.18)
PMIC_SPI_MOSI: rk3588 (R25.2 U3.L29), RK806-1 (U5.15)
PWRON_L: RK806-1 (C170.2 U5.4), Key Array (R181.1)
RD0_VS_N: LAN9696 (U1.B15), VSC_DP (C634.2)
RD0_VS_P: LAN9696 (U1.C15), VSC_DP (C633.2)
RESET_L: rk3588 (5 pins), RK806-1 (R172.1 U5.40), Key Array (R179.1)
RESET_L_: rk3588 (U54.3), IO_Expander_of_RP (U43.21)
RK_RX: rk3588 (R306.2), IO_Expander_of_RP (U44.18)
RK_TX: rk3588 (R305.2), IO_Expander_of_RP (U44.17)
RP_COMA_VSC: IO_Expander_of_RP (U43.27), Level_Shifter (U61.3)
RP_MDC_VSC: RP2350 (U35.16), Level_Shifter (U59.3)
RP_MDIO_0: RP2350 (U35.14), Level_Shifter (IC1.10)
RP_MDIO_1: RP2350 (U35.15), Level_Shifter (IC1.9)
RP_MDIO_VSC: RP2350 (U35.17), Level_Shifter (IC.8)
RP_RST_DP0: IO_Expander_of_RP (U43.25), Level_Shifter (U57.3)
RP_RST_DP1: IO_Expander_of_RP (U43.26), Level_Shifter (U58.3)
RP_RST_VSC: IO_Expander_of_RP (U43.28), Level_Shifter (U60.3)
RP_SCL: RP2350 (R194.1 U35.10 U63.6), IO_Expander_of_RP (U42.13 U43.12)
RP_SDA: RP2350 (R195.1 U35.9 U63.5), IO_Expander_of_RP (U42.11 U42.12 U43.13)
RST_VSC: VSC_DP (U50.M3), Level_Shifter (U60.4)
SARADC_VIN1_KEY/RECOVERY: rk3588 (J10.8 R128.1 U3.AL16), Key Array (R177.1 R178.2 U16.1)
SPI0_CsN: RP2350 (U35.33), IO_Expander_of_RP (U44.5)
SPI0_RX: RP2350 (U35.32), IO_Expander_of_RP (U44.3)
SPI0_SCK: RP2350 (U35.34), IO_Expander_of_RP (U44.4)
SPI0_TX: RP2350 (U35.35), IO_Expander_of_RP (U44.6)
SYS4V0_MODE_L: rk3588 (U3.T32), BoardSupply (R89.2)
TD0_VS_N: LAN9696 (U1.E15), VSC_DP (C631.2)
TD0_VS_P: LAN9696 (U1.F15), VSC_DP (C630.2)
TX_CLK: LAN9696 (U1.G18), 8841 (U45.25)
TX_ER: LAN9696 (U1.G17), 8841 (U45.26)
TXD0: LAN9696 (U1.F19), 8841 (U45.19)
TXD1: LAN9696 (U1.F18), 8841 (U45.20)
TXD2: LAN9696 (U1.F17), 8841 (U45.21)
TXD3: LAN9696 (U1.E19), 8841 (U45.22)
UART2_RX_M0_DEBUG: rk3588 (U3.R29), RS232 DBG_UART (R164.1)
UART2_TX_M0_DEBUG: rk3588 (U3.P29), RS232 DBG_UART (R165.1)
UART3_RX_M2: rk3588 (U3.AL27), RS232 DBG_UART (R170.2)
UART3_TX_M2: rk3588 (U3.AK27), RS232 DBG_UART (R171.2)
VSC_COMA: VSC_DP (U50.L3), Level_Shifter (R285.1 U61.4)
VSC_MDC: VSC_DP (U50.P2), Level_Shifter (U59.4)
